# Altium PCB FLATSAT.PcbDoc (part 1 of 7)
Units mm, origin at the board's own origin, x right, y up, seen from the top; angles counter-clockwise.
Board outline 430 x 350 mm, 5 copper layers (Top Layer, Internal Plane 1, Internal Plane 2, DELETEME, Bottom Layer); 808 components, 852 nets, 6407 pads, 939 vias.
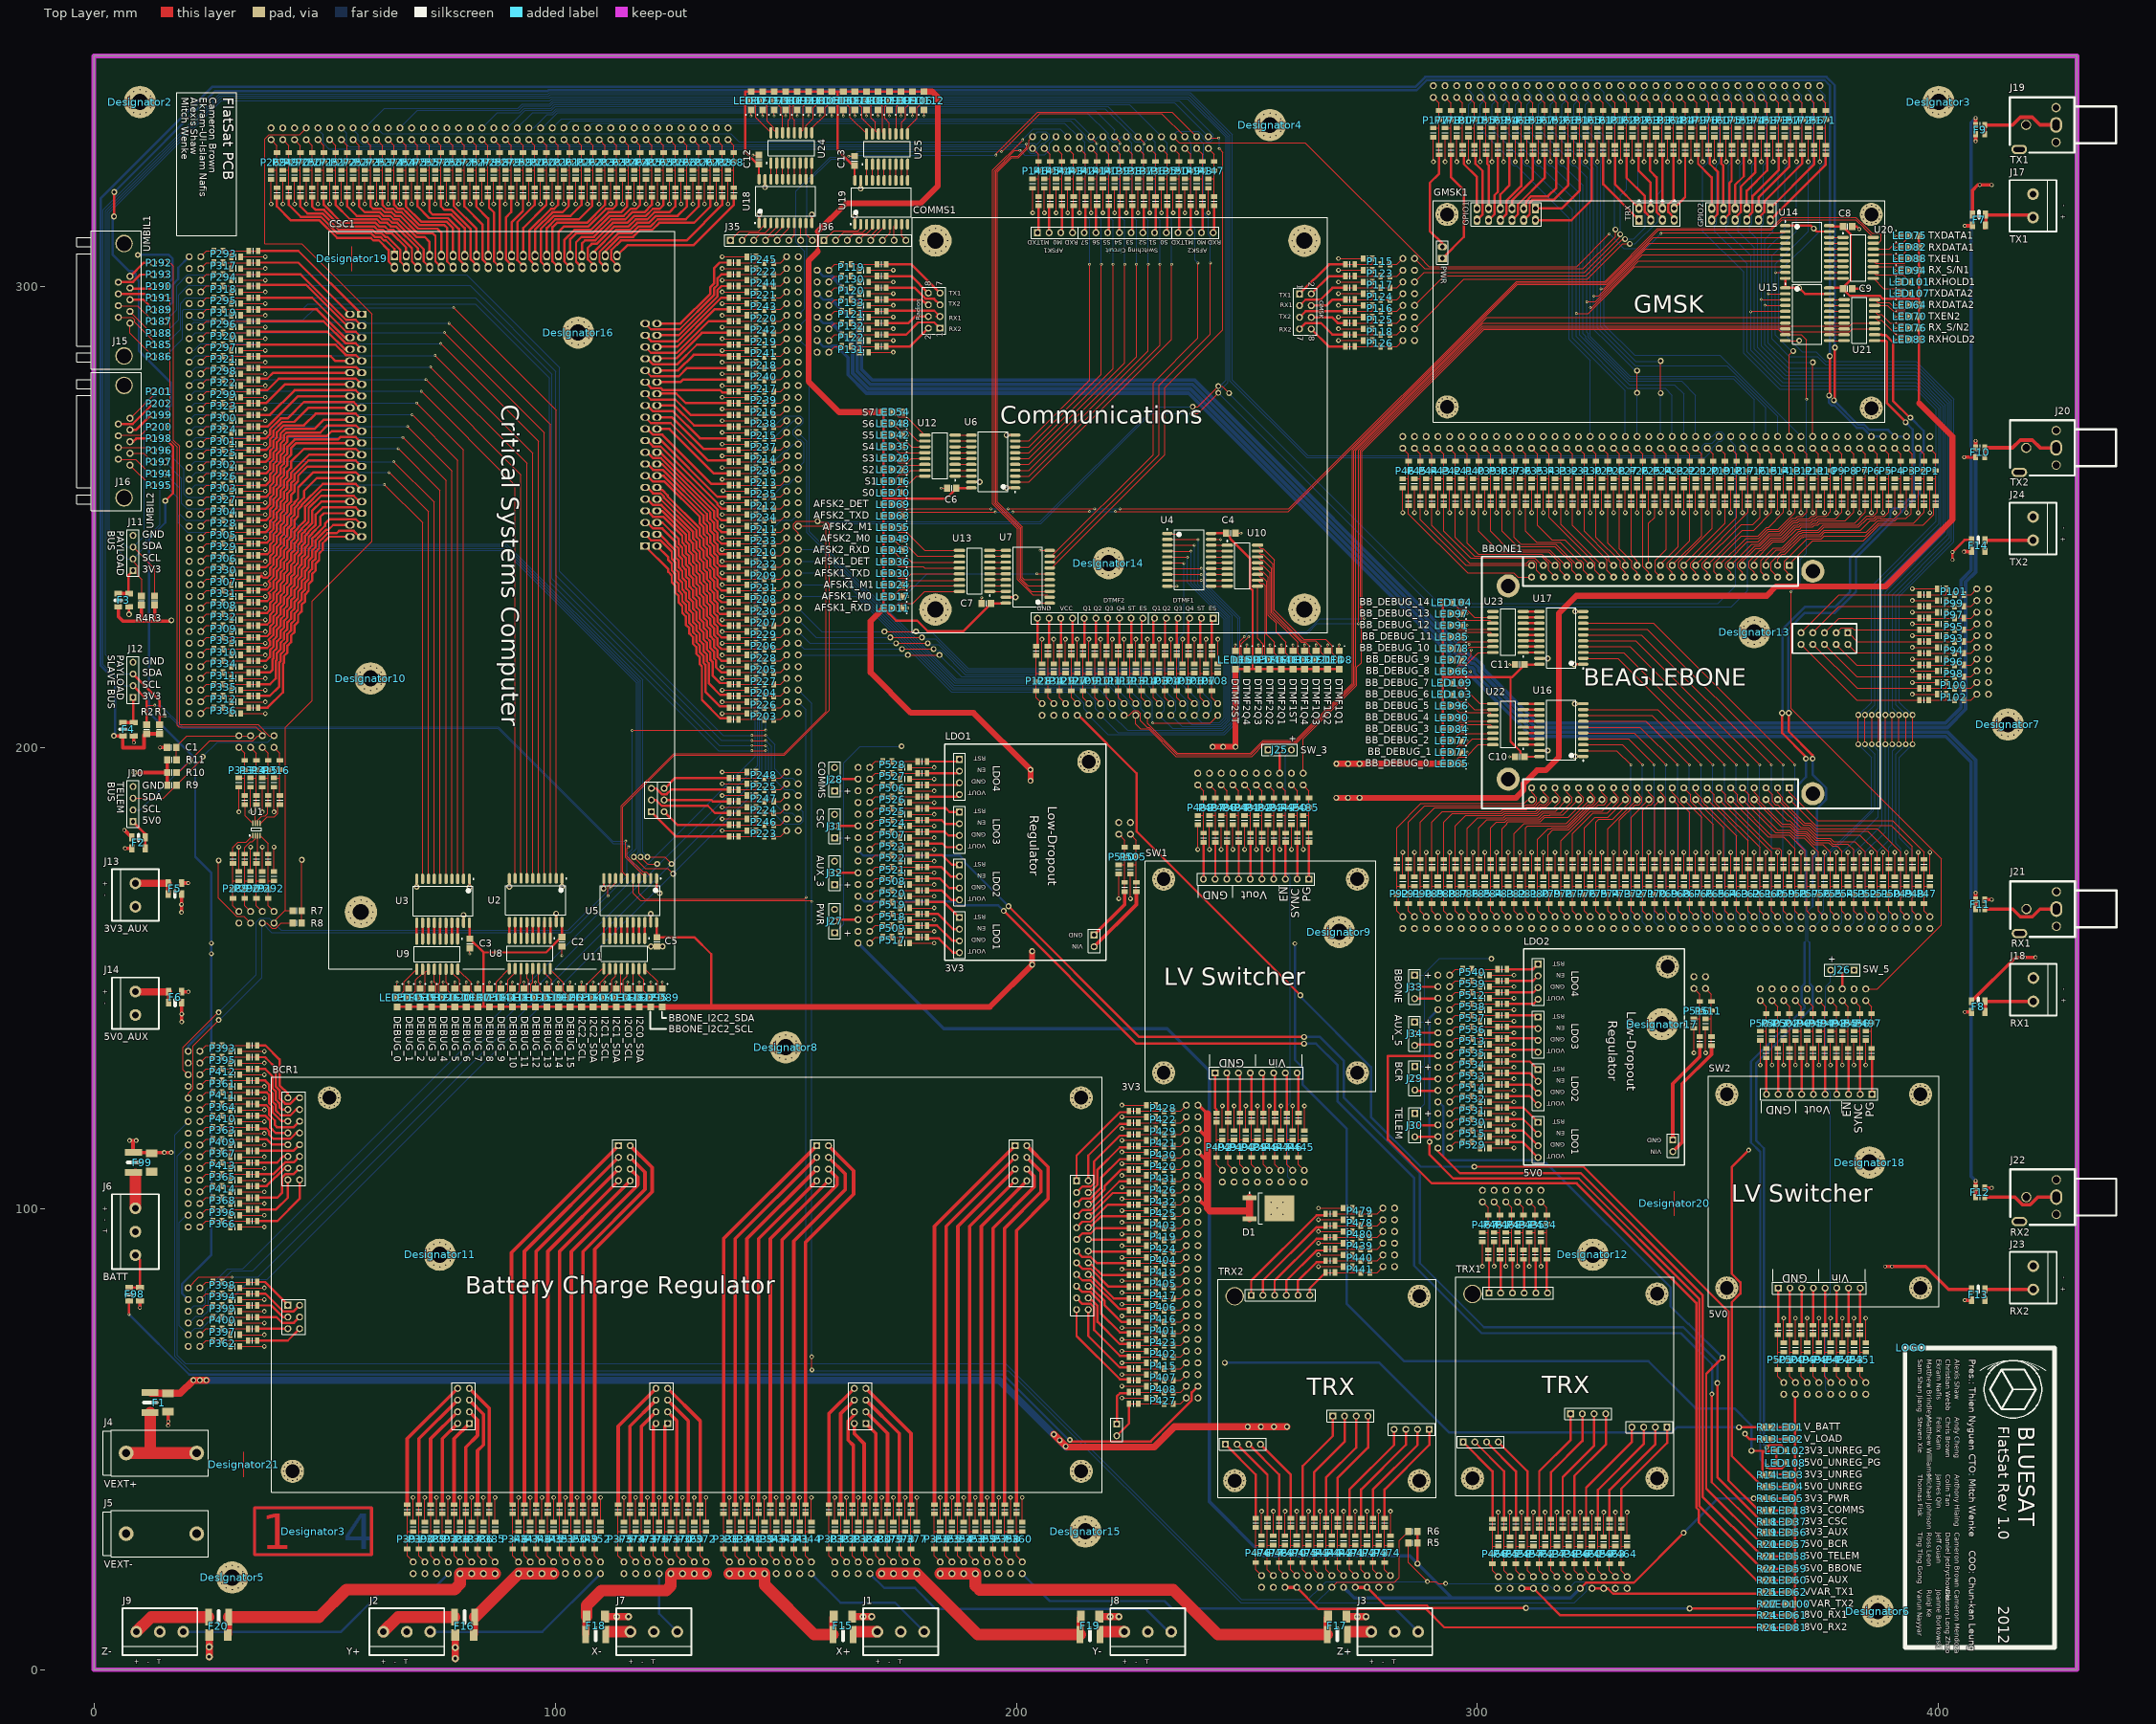
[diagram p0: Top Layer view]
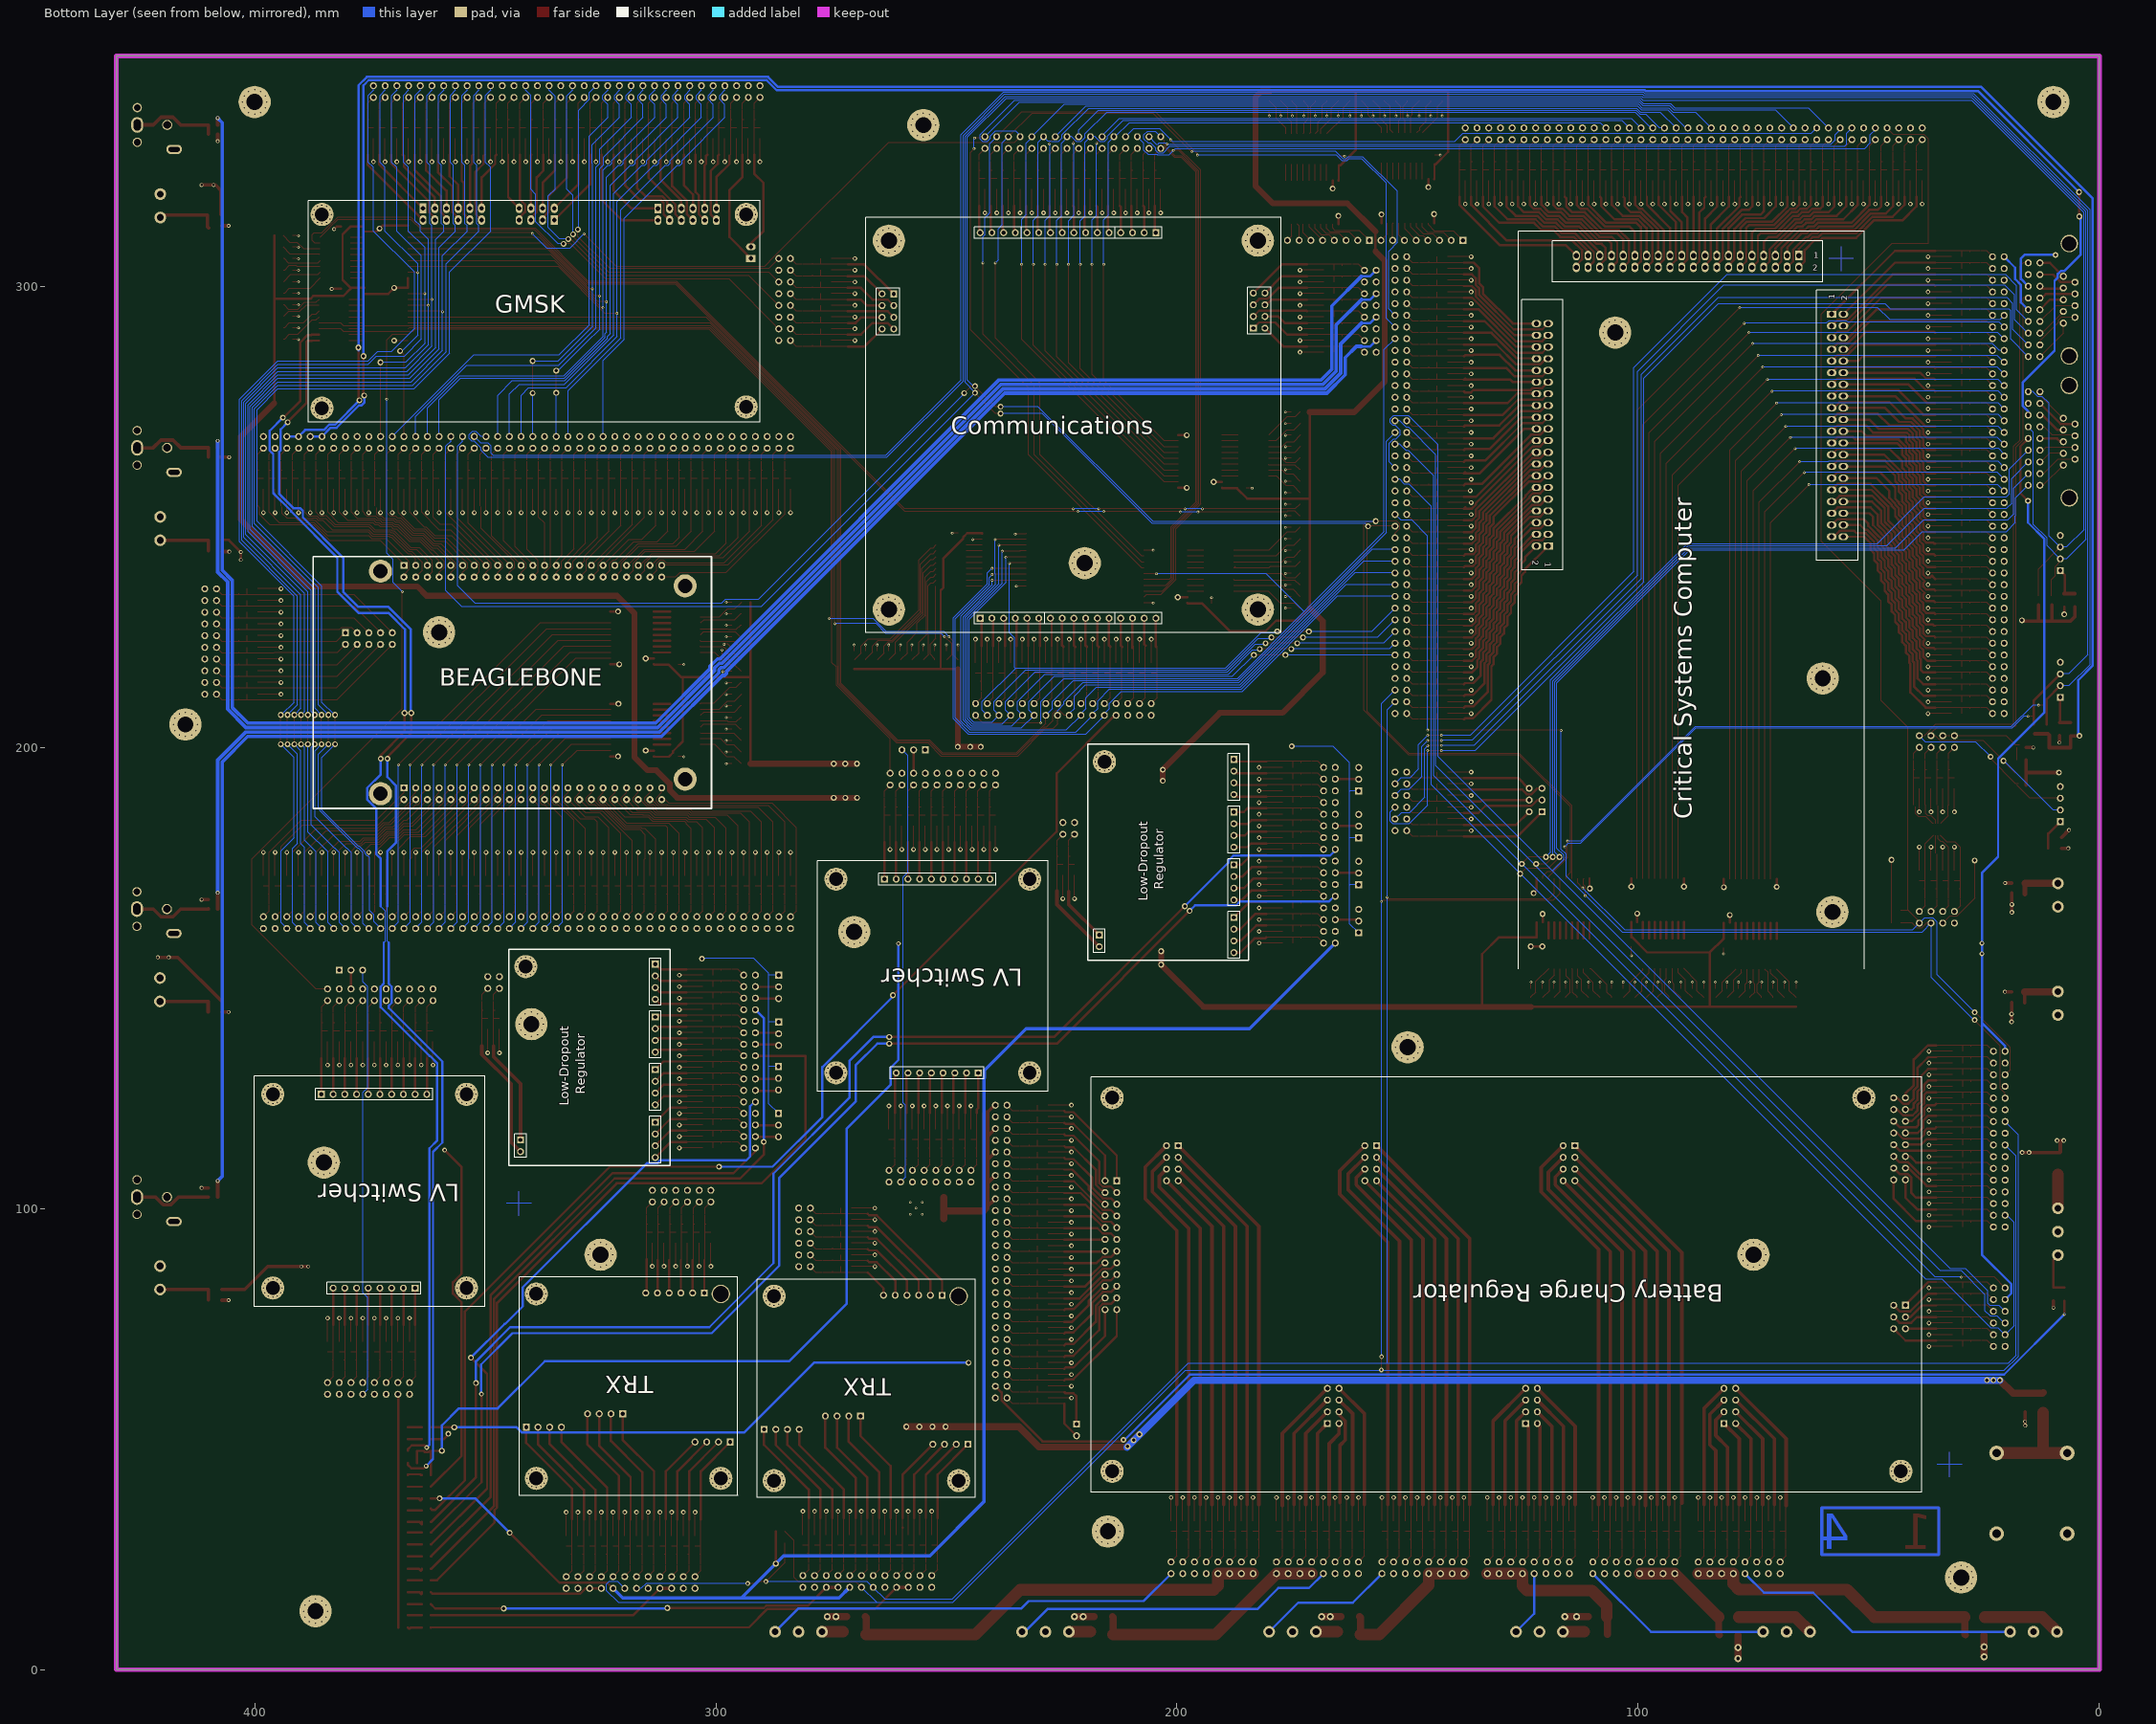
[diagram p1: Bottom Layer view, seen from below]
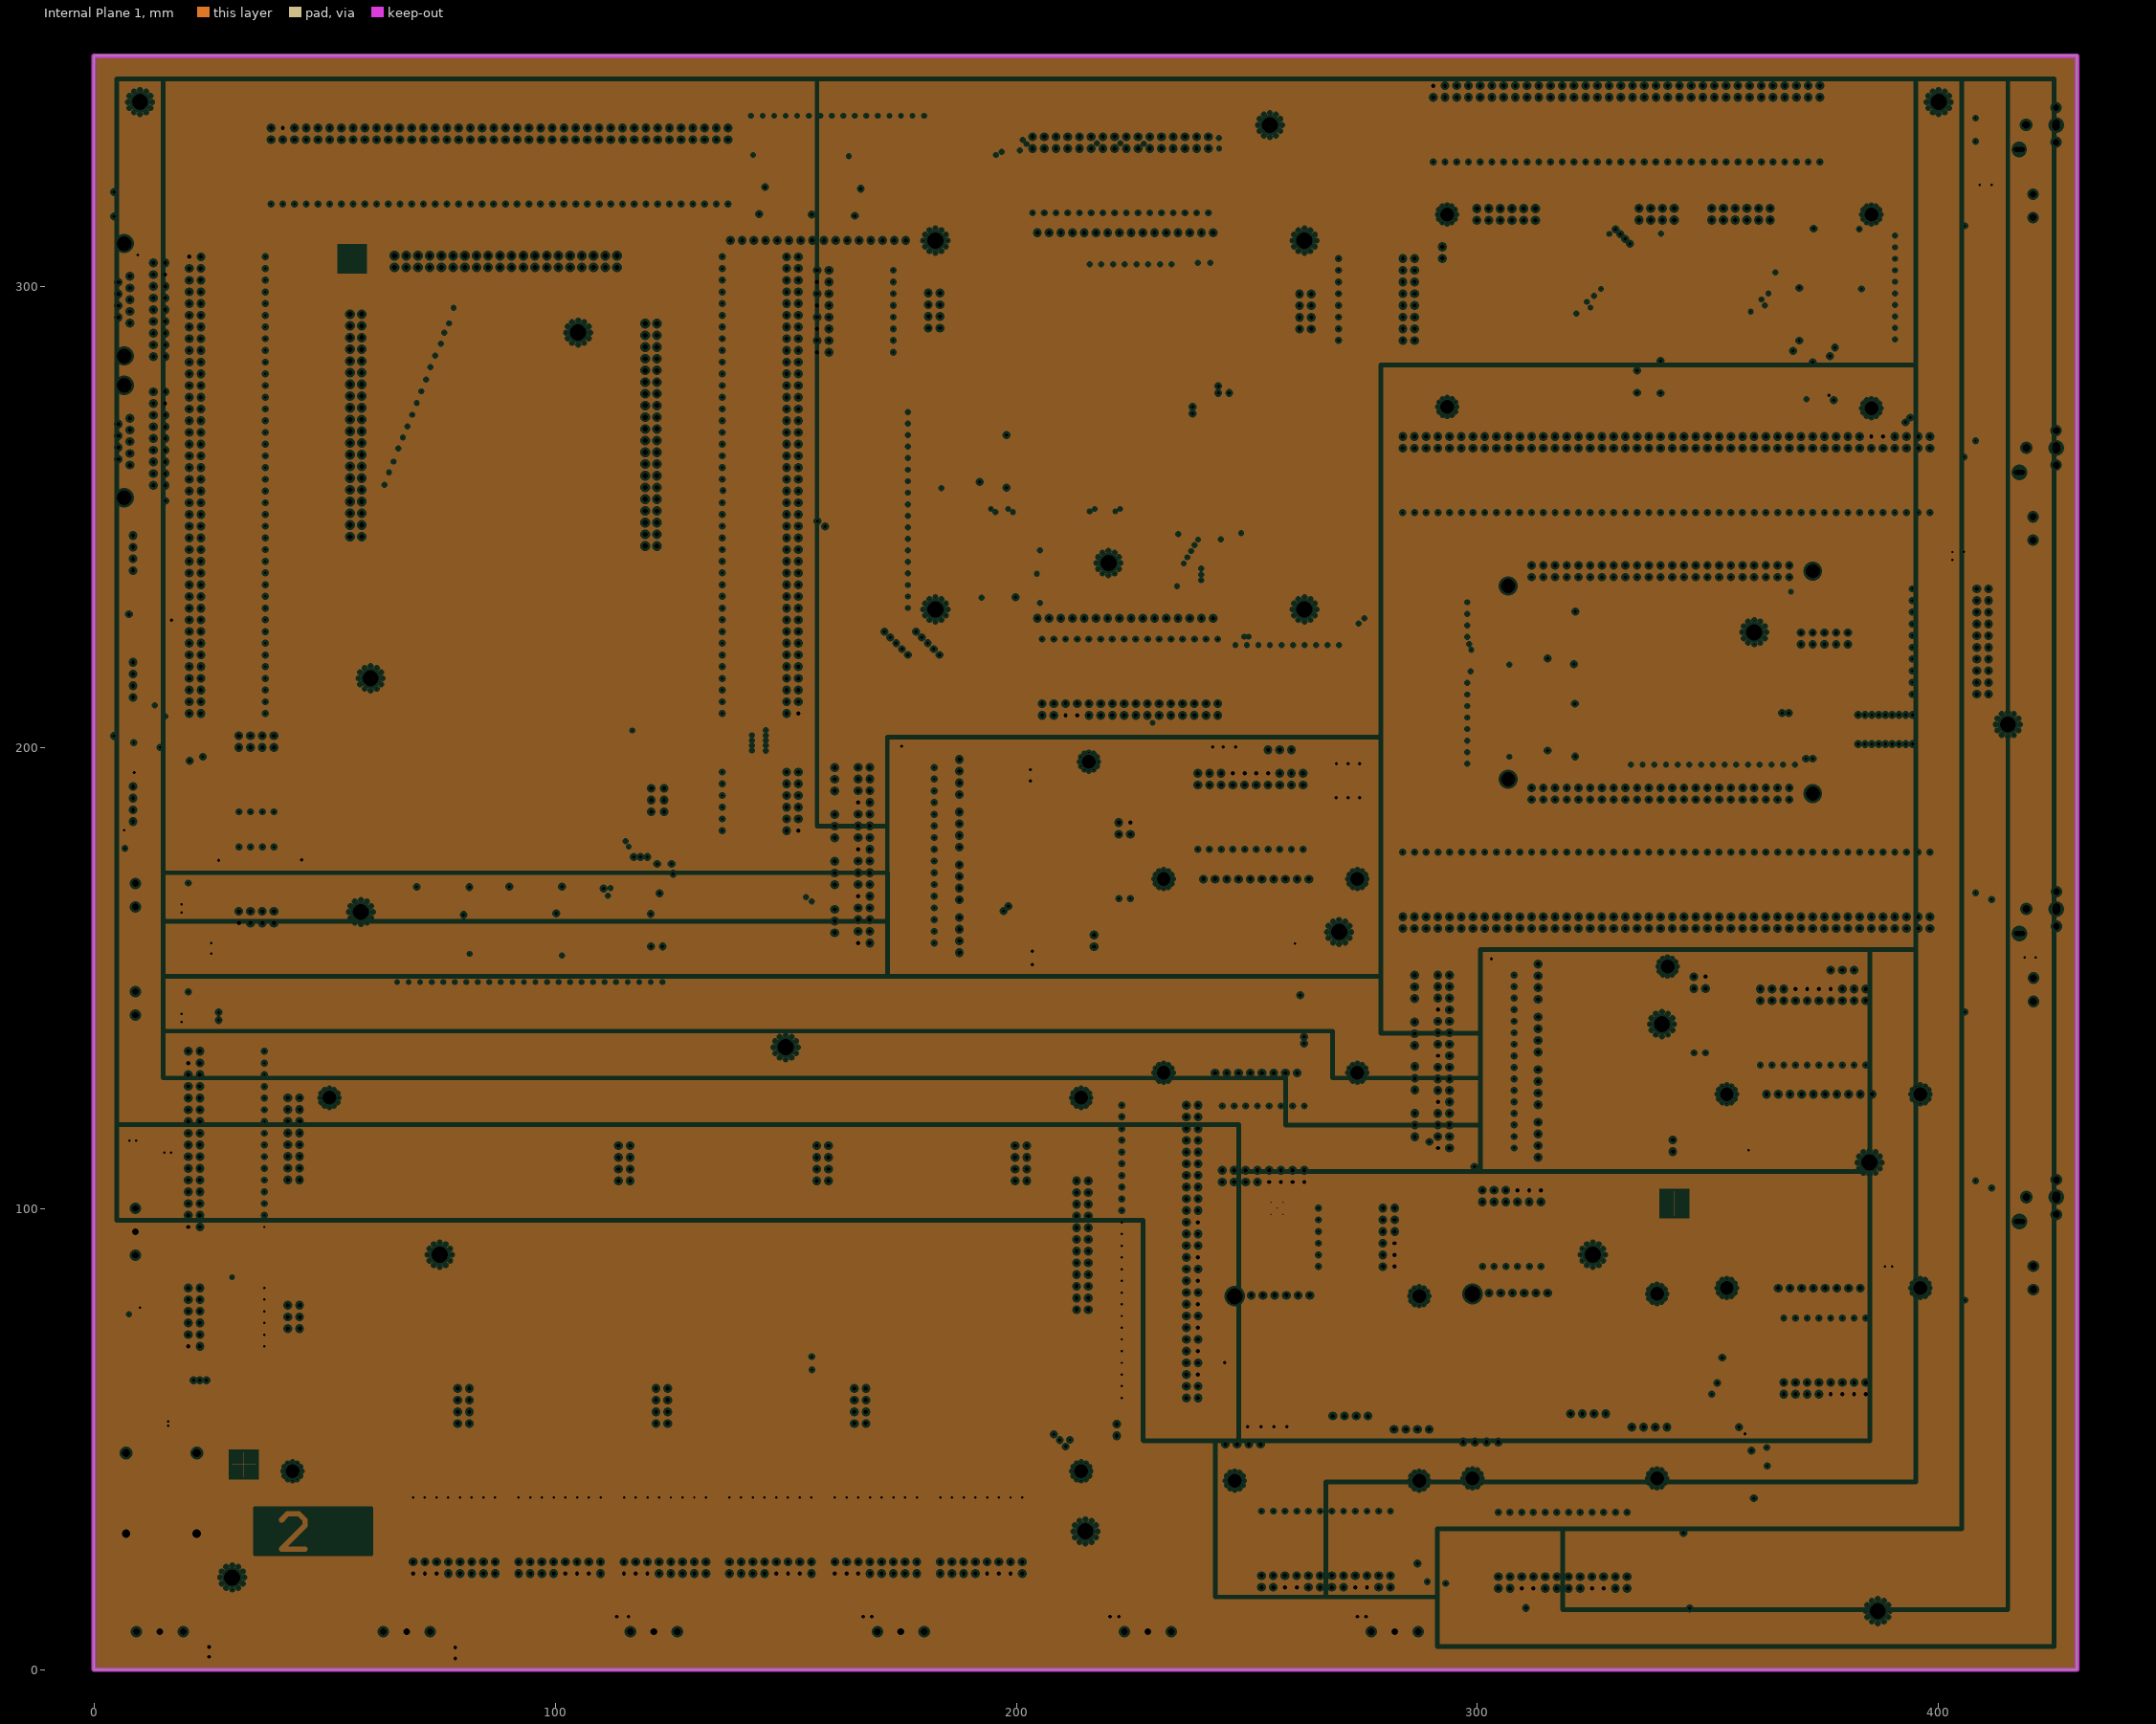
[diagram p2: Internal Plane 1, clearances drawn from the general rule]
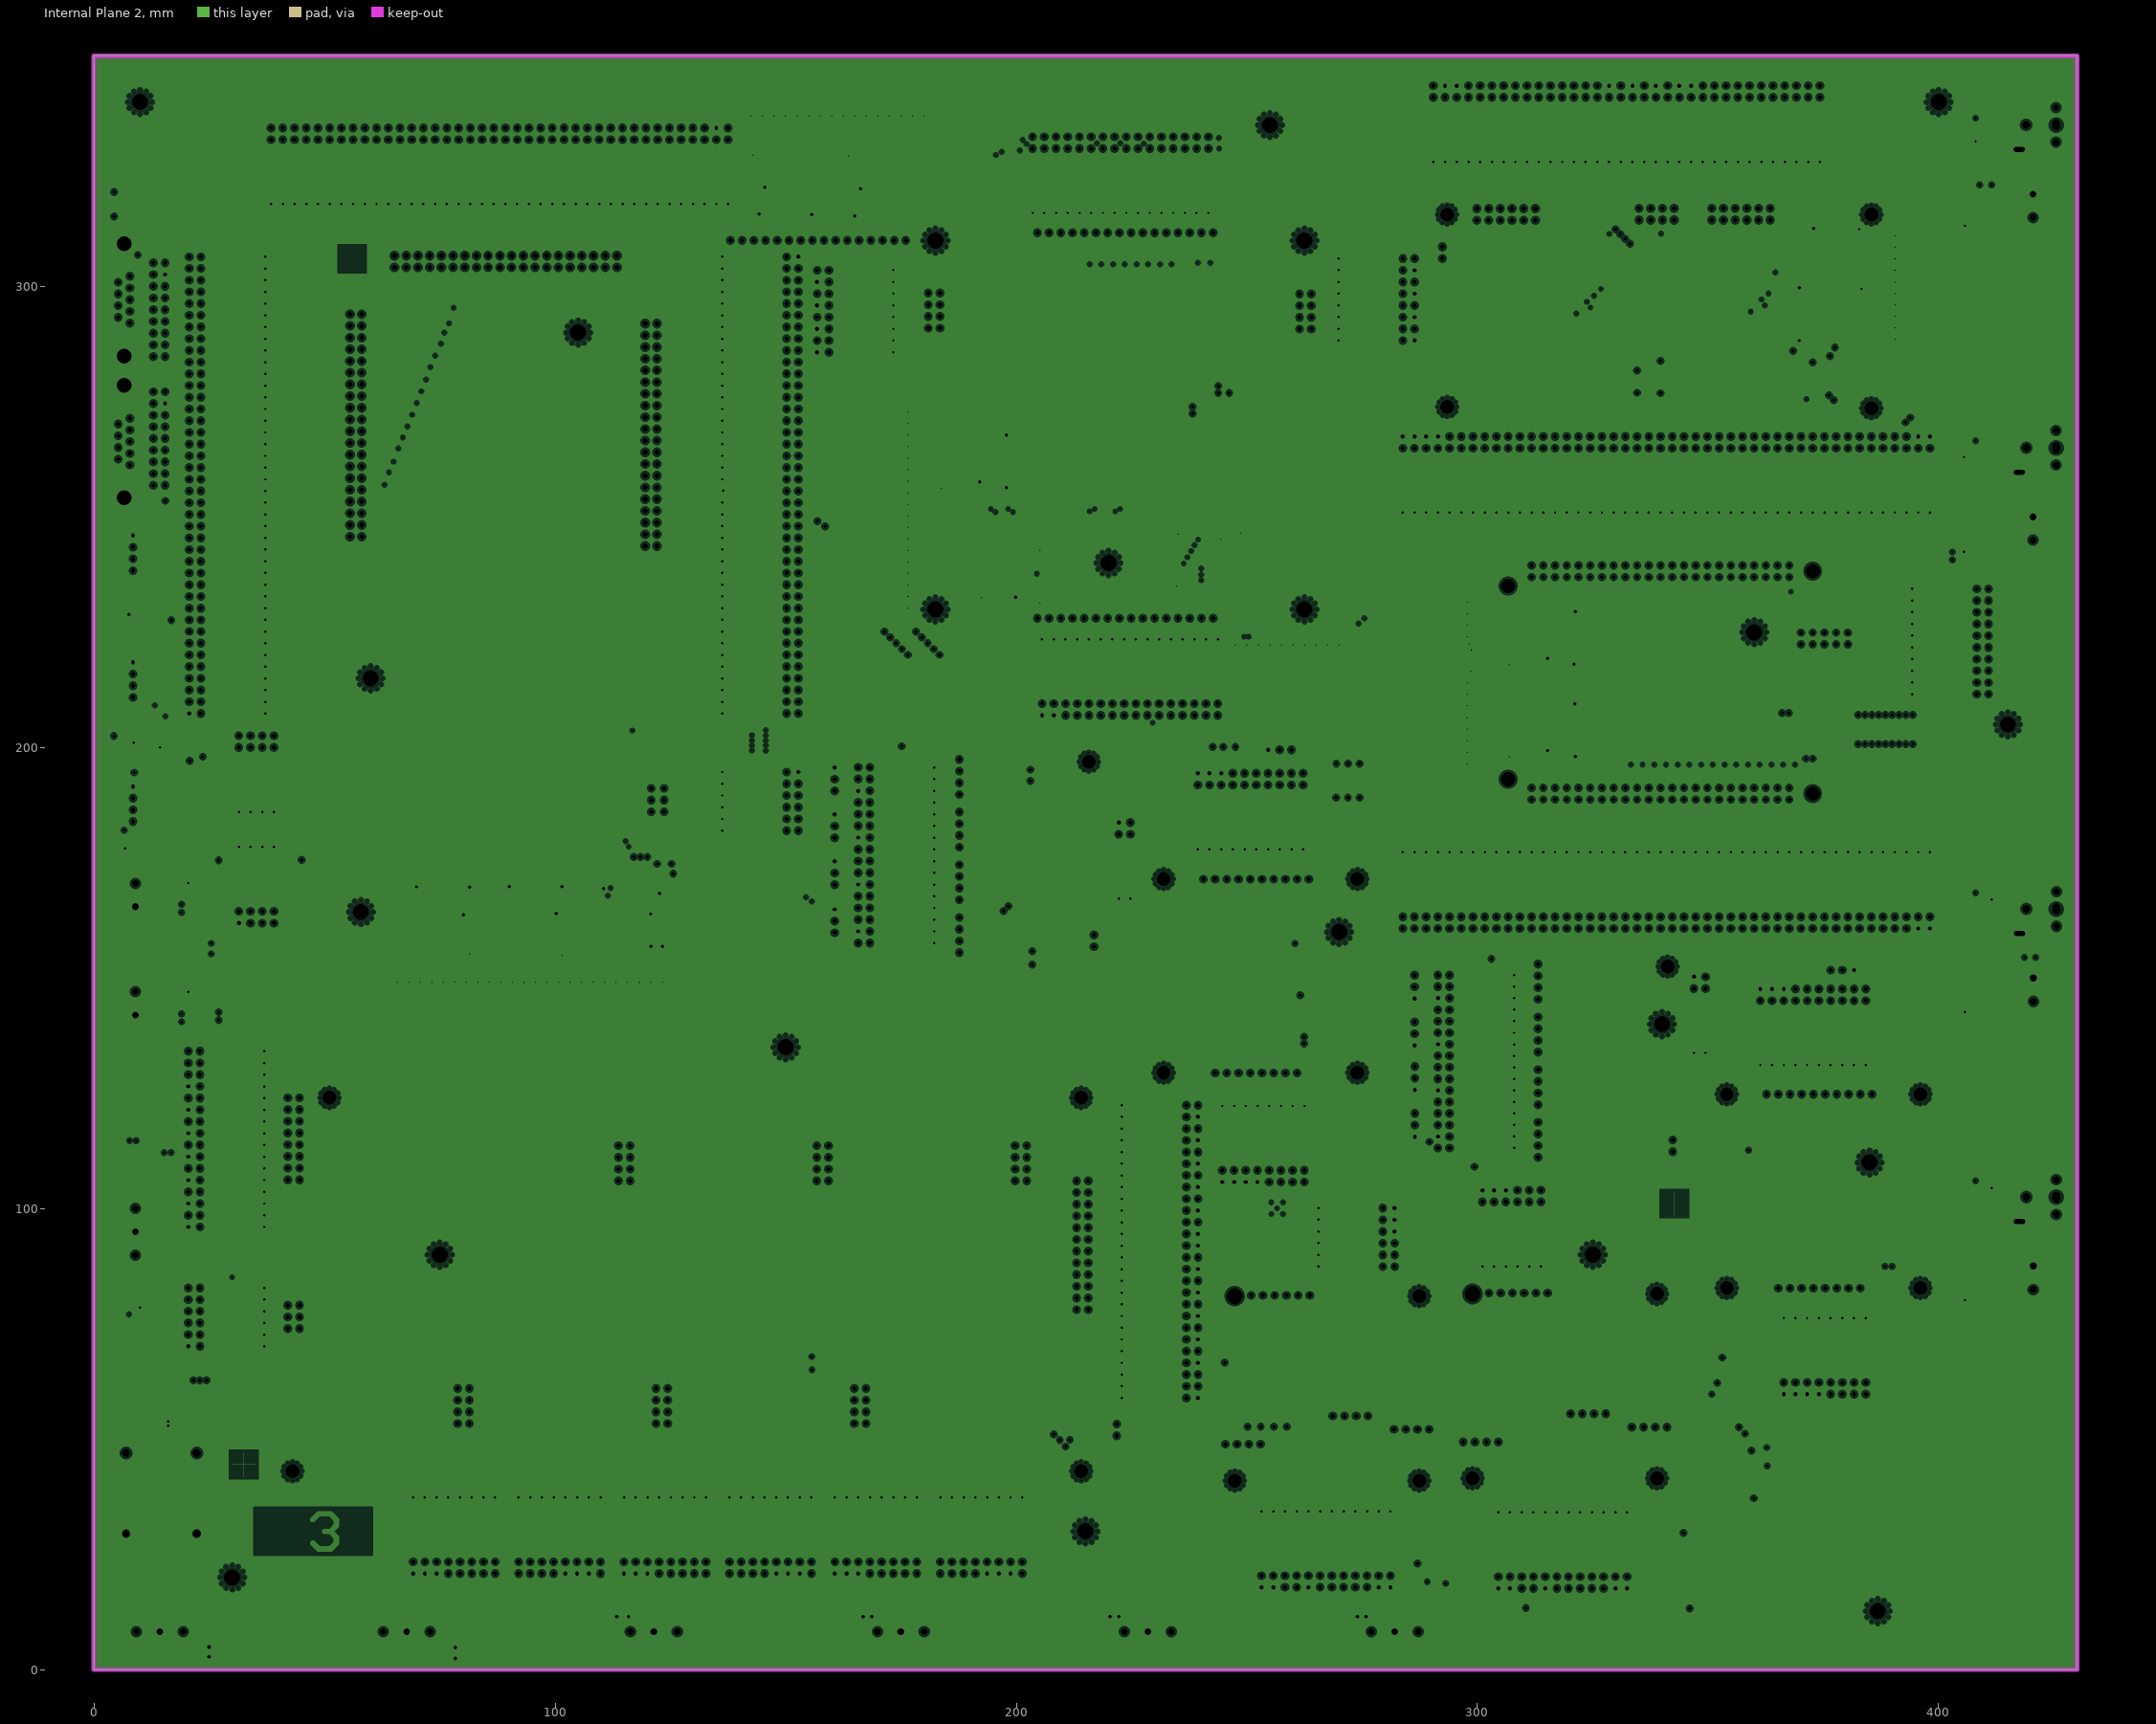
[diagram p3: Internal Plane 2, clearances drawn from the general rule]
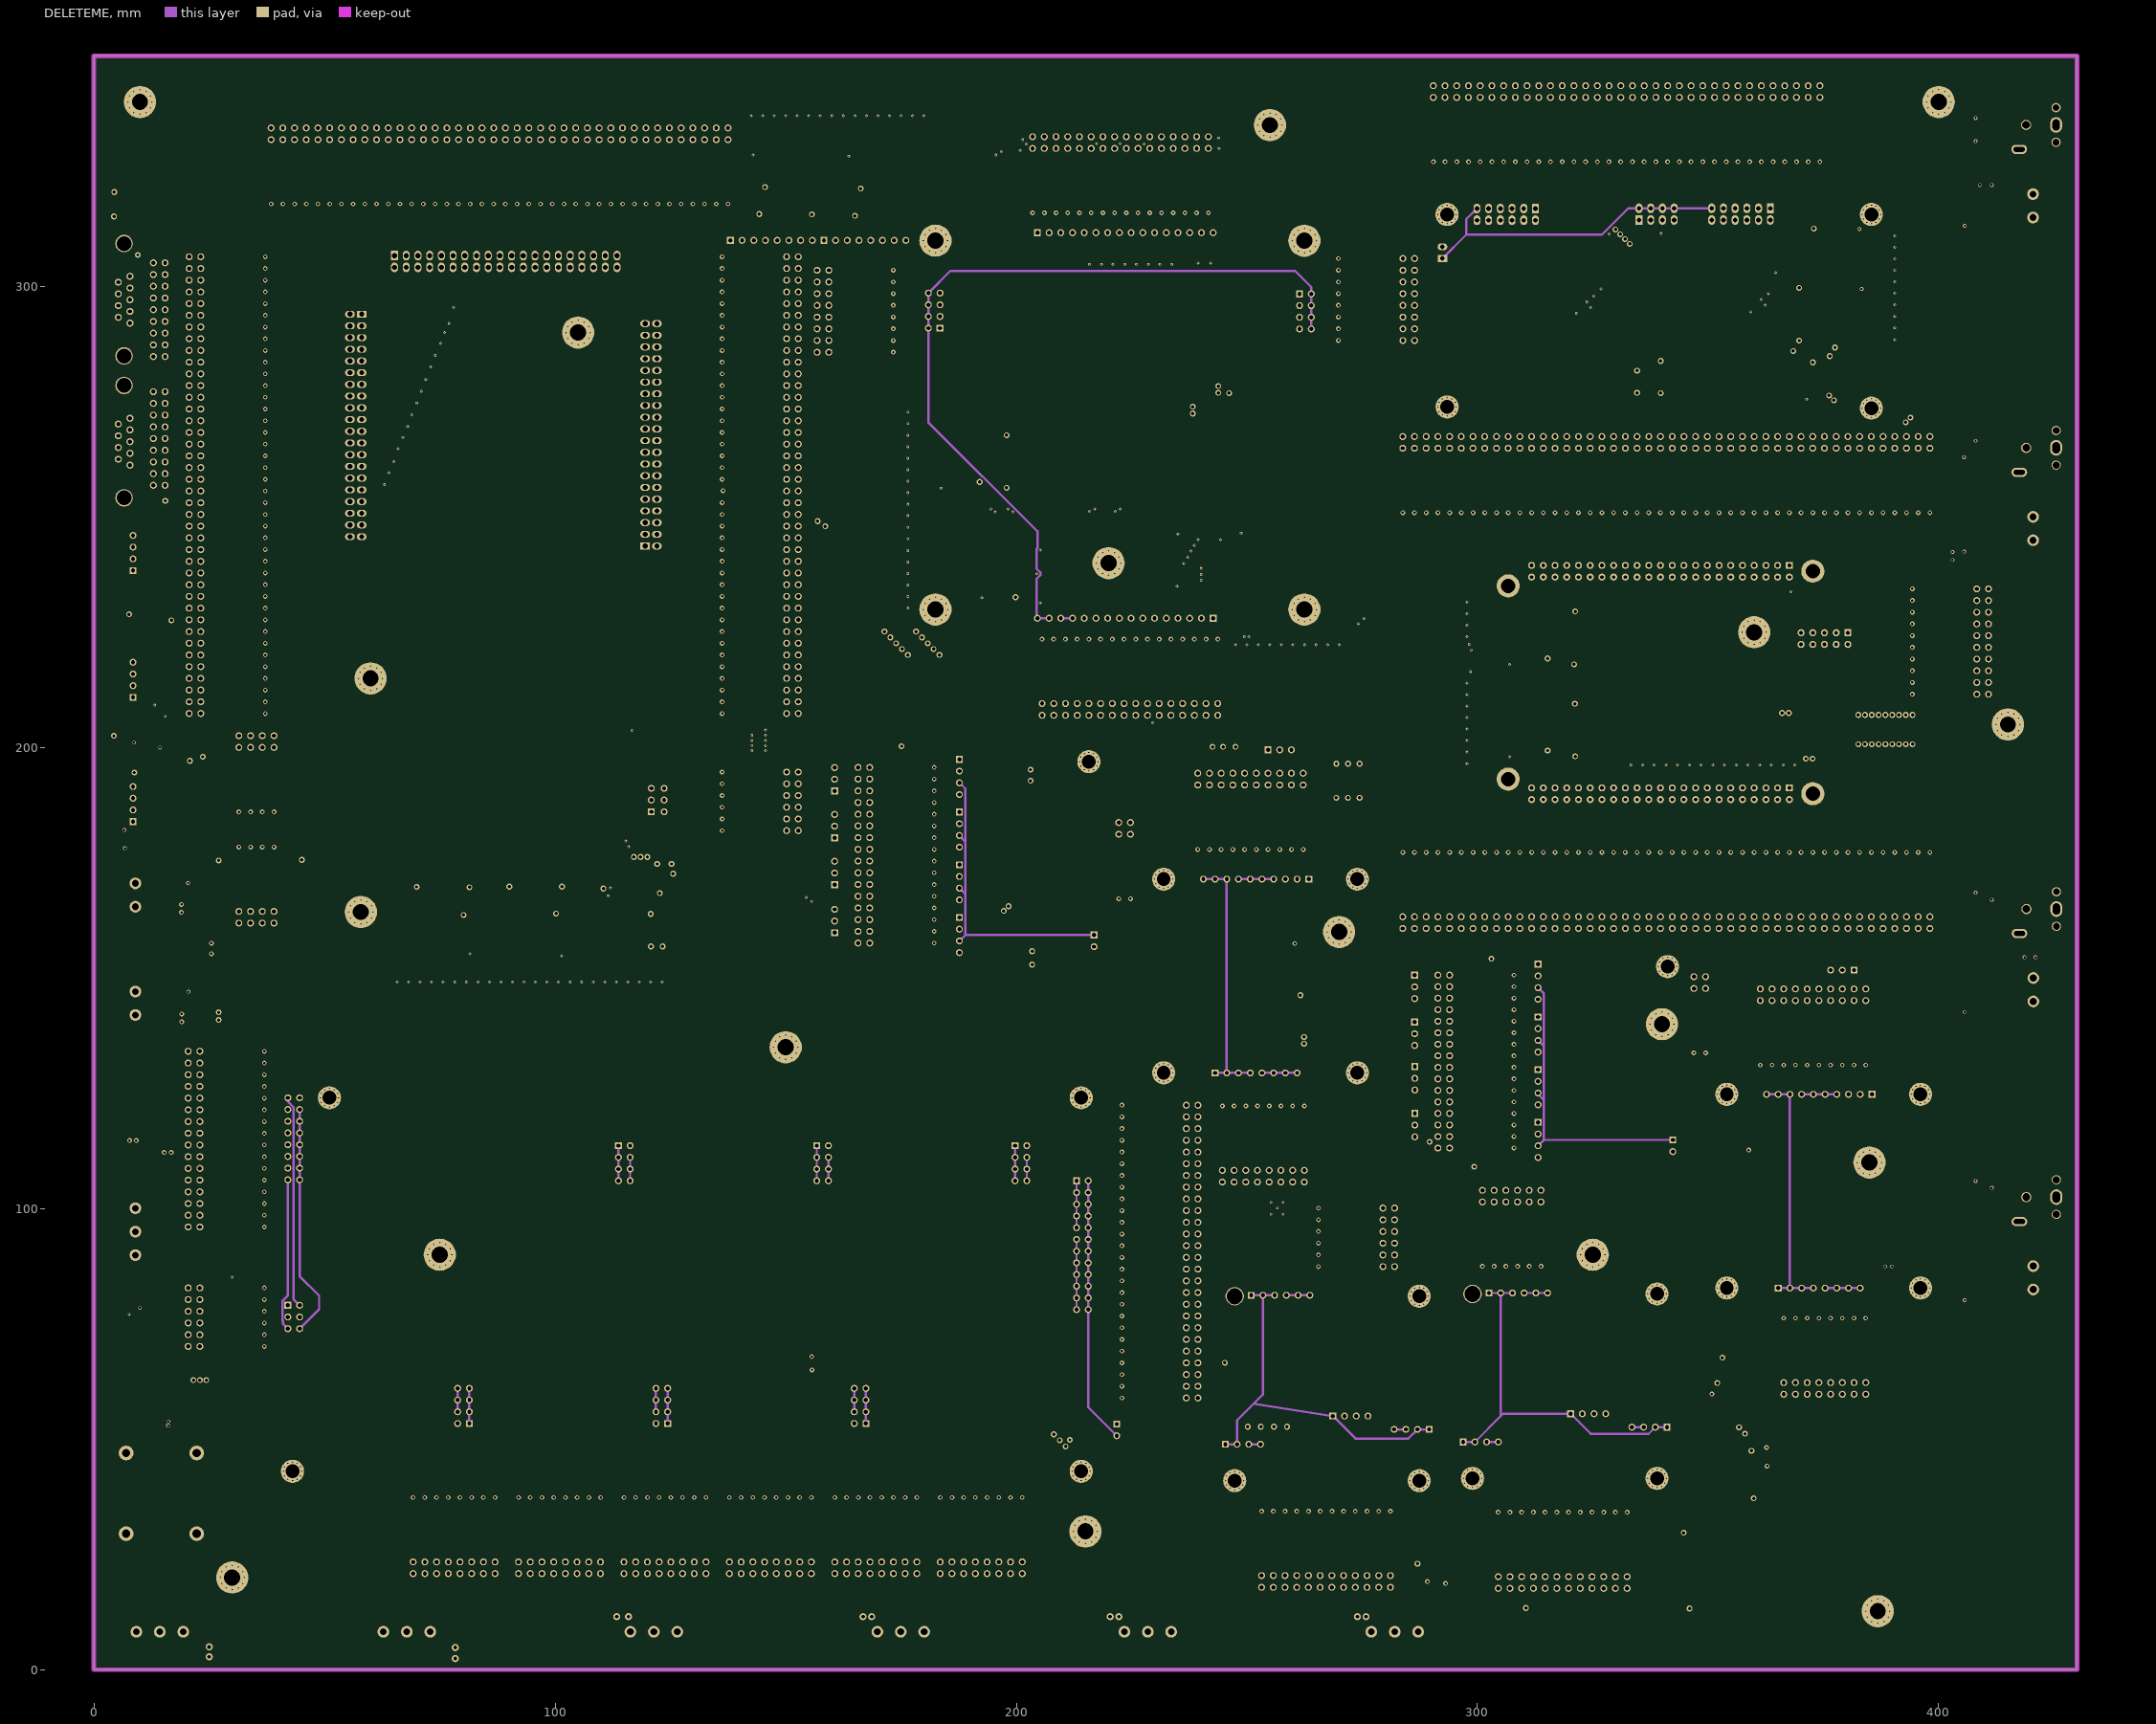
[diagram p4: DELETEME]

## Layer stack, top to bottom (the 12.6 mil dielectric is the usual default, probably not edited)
Top Layer: signal copper 0.0356
Dielectric: core 0.32, FR-4, Dk 4.8
Internal Plane 1: plane copper 0.0356, net (Multiple Nets)
Dielectric: prepreg 0.32, FR-4, Dk 4.8
Internal Plane 2: plane copper 0.0356, net GND
Dielectric: core 0.32, FR-4, Dk 4.8
DELETEME: signal copper 0.0356
Dielectric: prepreg 0.32, FR-4, Dk 4.8
Bottom Layer: signal copper 0.0356

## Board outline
0,0 0,350 430,350 430,0

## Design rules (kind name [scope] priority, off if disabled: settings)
Clearance [All] p1: gap=0.178
HoleSize [All] p1: absolutevalues=TRUE maxlimit=25.4 minlimit=0.025 maxpercent=80.000 minpercent=20.000
MinimumSolderMaskSliver [NOT InNet('GND') vs NOT InNet('GND')] p1: minsoldermaskwidth=0.152
PlaneClearance [All] p1: clearance=0.508
PlaneConnect [All] p1: planeconnectstyle=Relief reliefexpansion=0.508 reliefentries=4 reliefconductorwidth=0.254 reliefairgap=0.254
PolygonConnect [All] p1: connectstyle=Relief reliefconductorwidth=0.254 reliefentries=4 polygonreliefangle="90 Angle"
RoutingVias [All] p1: holewidth=0.711 width=1.27 viastyle="Through Hole" minholewidth=0.508 minwidth=1.016 maxholewidth=0.711 maxwidth=1.27
ShortCircuit ShortCircuit_1 [All] p1: allowed=FALSE
ShortCircuit [All] p2: allowed=FALSE
SilkToSilkClearance [All] p1 off: silktosilkclearance=0.003
SilkscreenOverComponentPads [All] p1: minsilkscreentomaskgap=0.003
SolderMaskExpansion [All] p1: expansion=0.102
Width [All] p1: maxlimit=2.54 minlimit=0.152 preferedwidth=0.508
21 further rules are at their usual default settings.

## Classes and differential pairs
component class LED_BANK_PWR: LED1 LED2 LED3 LED4 LED5 LED18 LED37 LED56 LED57 LED58 LED59 LED60 LED61 LED62 LED81 LED100 R12 R13 R14 R15 R16 R17 R18 R19 R20 R21 R22 R23 R24 R25 R26 R27
component class LED_BANK_12: C13 J36 LED68 LED74 LED80 LED87 LED93 LED99 LED106 LED112 U19 U25
component class LED_BANK_11: C12 J35 LED67 LED73 LED79 LED86 LED92 LED98 LED105 LED111 U18 U24
component class LED_BANK_10: C11 LED66 LED72 LED78 LED85 LED91 LED97 LED104 U17 U23
component class LED_BANK_9: C10 LED65 LED71 LED77 LED84 LED90 LED96 LED103 LED109 U16 U22
component class LED_BANK_8: C9 LED64 LED70 LED76 LED83 LED89 LED95 LED102 LED108 U15 U21
component class LED_BANK_7: C8 LED63 LED69 LED75 LED82 LED88 LED94 LED101 LED107 U14 U20
component class LED_BANK_6: C7 LED11 LED17 LED24 LED30 LED36 LED43 LED49 LED55 U7 U13
component class LED_BANK_5: C6 LED10 LED16 LED23 LED29 LED35 LED42 LED48 LED54 U6 U12
component class LED_BANK_4: C5 LED9 LED15 LED22 LED28 LED34 LED41 LED47 LED53 U5 U11
component class LED_BANK_3: C4 LED8 LED14 LED21 LED27 LED33 LED40 LED46 LED52 U4 U10
component class LED_BANK_2: C3 LED7 LED13 LED20 LED26 LED32 LED39 LED45 LED51 U3 U9
component class LED_BANK_1: C2 LED6 LED12 LED19 LED25 LED31 LED38 LED44 LED50 U2 U8
component class BBONE: BBONE1 P1 P2 P3 P4 P5 P6 P7 P8 P9 P10 P11 P12 P13 P14 P15 P16 P17 P18 P19 P20 P21 P22 P23 P24 P25 P26 P27 P28 P29 P30 P31 P32 P33 P34 P35 P36 P37 P38 P39 P40 P41 P42 P43 P44 P45 P46 P47 P48 P49 P50 P51 P52 P53 P54 P55 P56 P57 P58 P59 P60 P61 P62 P63 P64 P65 P66 P67 P68 P69 P70 P71 P72 P73 P74 P75 P76 P77 P78 P79 P80 P81 P82 P83 P84 P85 P86 P87 P88 P89 P90 P91 P92 P93 P94 P95 P96 P97 P98 P99 P100 P101 P102
component class CONNECTORS: F1 F2 F3 F4 F5 F6 F7 F8 F9 F10 F11 F12 F13 F14 F98 F99 J1 J2 J3 J4 J5 J6 J7 J8 J9 J10 J11 J12 J13 J14 J15 J17 J18 J19 J20 J21 J22 J23 J24 P185 P186 P187 P188 P189 P190 P191 P192 P193 P194 P195 P196 P197 P198 P199 P200 P201 P202
component class CSC: CSC1 P203 P204 P205 P206 P207 P208 P209 P210 P211 P212 P213 P214 P215 P216 P217 P218 P219 P220 P221 P222 P223 P224 P225 P226 P227 P228 P229 P230 P231 P232 P233 P234 P235 P236 P237 P238 P239 P240 P241 P242 P243 P244 P245 P246 P247 P248 P249 P250 P251 P252 P253 P254 P255 P256 P257 P258 P259 P260 P261 P262 P263 P264 P265 P266 P267 P268 P269 P270 P271 P272 P273 P274 P275 P276 P277 P278 P279 P280 P281 P282 P283 P284 P285 P286 P287 P288 P289 P290 P291 P292 P293 P294 P295 P296 P297 P298 P299 P300 P301 P302 P303 P304 P305 P306 P307 P308 P309 P310 P311 P312 P313 P314 P315 P316 P317 P318 P319 P320 P321 P322 P323 P324 P325 P326 P327 P328 P329 P330 P331 P332 P333 P334 P335 P336 R5 R6 R7 R8 U1
component class PWR_GEN: BCR1 D1 F15 F16 F17 F18 F19 F20 P321_1 P337 P338 P339 P340 P341 P342 P343 P344 P345 P346 P347 P348 P349 P350 P351 P352 P353 P354 P355 P356 P357 P358 P359 P360 P361 P362 P363 P364 P365 P366 P367 P368 P369 P370 P371 P372 P373 P374 P375 P376 P377 P378 P379 P380 P381 P382 P383 P384 P385 P386 P387 P388 P389 P390 P391 P392 P393 P394 P395 P396 P397 P398 P399 P400 P401 P402 P403 P404 P405 P406 P407 P408 P409 P410 P411 P412 P413 P414 P415 P416 P417 P418 P419 P420 P421 P422 P423 P424 P425 P426 P427 P428 P429 P430 P431 P432
component class GMSK: GMSK1 P151 P152 P153 P154 P155 P156 P157 P158 P159 P160 P161 P162 P163 P164 P165 P166 P167 P168 P169 P170 P171 P172 P173 P174 P175 P176 P177 P178 P179 P180 P181 P182 P183 P184
component class COMMSB: COMMS1 P103 P104 P105 P106 P107 P108 P109 P110 P111 P112 P113 P114 P115 P116 P117 P118 P119 P120 P121 P122 P123 P124 P125 P126 P127 P128 P129 P130 P131 P132 P133 P134 P135 P136 P137 P138 P139 P140 P141 P142 P143 P144 P145 P146 P147 P148 P149 P150
component class LDO1: J27 J28 J31 J32 LDO1 P505 P506 P507 P508 P509 P510 P517 P518 P519 P520 P521 P522 P523 P524 P525 P526 P527 P528
component class LDO2: J29 J30 J33 J34 LDO2 P511 P512 P513 P514 P515 P516 P529 P530 P531 P532 P533 P534 P535 P536 P537 P538 P539 P540
component class SW1: J25 P445 P446 P447 P448 P449 P450 P481 P482 P483 P484 P485 P486 P487 P488 P489 P490 P491 P492 SW1
component class SW2: J26 P451 P452 P453 P454 P455 P456 P493 P494 P495 P496 P497 P498 P499 P500 P501 P502 P503 P504 SW2
component class TRX1: P433 P434 P435 P436 P437 P438 P457 P458 P459 P460 P461 P462 P463 P464 P465 P466 P467 P468 TRX1
component class TRX2: P439 P440 P441 P442 P443 P444 P469 P470 P471 P472 P473 P474 P475 P476 P477 P478 P479 P480 TRX2

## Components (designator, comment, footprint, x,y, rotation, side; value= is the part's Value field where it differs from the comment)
BBONE1 "Beagle_Bone" Beaglebone 300.943,241.41 r0 top locked
BCR1 "BCR" BCR 218.571,128.532 r180 top locked
C1 "0805 Cap" 6-0805_M 16.875,200.025 r0 top
C2 "" 6-0805_M 101.505,157.875 r90 top
C3 "" 6-0805_M 81.5,157.5 r90 top
C4 "" 6-0805_M 246.5,246.5 r180 top
C5 "" 6-0805_M 122.073,157.85 r90 top
C6 "" 6-0805_M 186,256.25 r0 top
C7 "" 6-0805_M 193.5,231.25 r0 top
C8 "" 6-0805_M 380.25,313 r180 top
C9 "" 6-0805_M 380.25,299.5 r180 top
C10 "" 6-0805_M 309.171,198 r0 top
C11 "" 6-0805_M 309.171,218 r0 top
C12 "" 6-0805_M 144.18,327.5 r270 top
C13 "" 6-0805_M 164.93,327.25 r270 top
COMMS1 "COMMS" Communications 177.473,224.924 r0 top locked
CSC1 "Critical Systems Computer" CSC 50.944,311.951 r270 top locked
D1 "50WQ03FN" TO229P990X238-3N 254.648,100.076 r0 top
Designator2 "Comment" HOLE3.5 10,340 r0 top
Designator3 "Comment" "Layer Plot" 47.5,30 r0 top
Designator3 "Comment" HOLE3.5 400,340 r0 top
Designator4 "Comment" HOLE3.5 255,335 r0 top
Designator5 "Comment" HOLE3.5 30,20 r0 top
Designator6 "Comment" HOLE3.5 386.8,12.7 r0 top
Designator7 "Comment" HOLE3.5 415,205 r0 top
Designator8 "Comment" HOLE3.5 150,135 r0 top
Designator9 "Comment" HOLE3.5 270,160 r0 top
Designator10 "Comment" HOLE3.5 60,215 r0 top
Designator11 "Comment" HOLE3.5 75,90 r0 top
Designator12 "Comment" HOLE3.5 325,90 r0 top
Designator13 "Comment" HOLE3.5 360,225 r0 top
Designator14 "Comment" HOLE3.5 220,240 r0 top
Designator15 "Comment" HOLE3.5 215,30 r0 top
Designator16 "Comment" HOLE3.5 105,290 r0 top
Designator17 "Comment" HOLE3.5 340,140 r0 top
Designator18 "Comment" HOLE3.5 385,110 r0 top
Designator19 "Comment" "Registration Check" 56,306 r0 top
Designator20 "Comment" "Registration Check" 342.7,101.1 r0 top
Designator21 "Comment" "Registration Check" 32.5,44.5 r0 top
F1 "FilterSola" FILTERSOLA 16.097,57.94 r90 top
F2 "FilterPwr" FILTERPWR 9.675,178.15 r0 top
F3 "FilterPwr" FILTERPWR 7.645,231.953 r90 top
F4 "FilterPwr" FILTERPWR 8.636,203.962 r90 top
F5 "FilterPwr" FILTERPWR 17.575,170.6 r180 top
F6 "FilterPwr" FILTERPWR 17.624,147.036 r180 top
F7 "FilterPwr" FILTERPWR 408.75,313.25 r0 top
F8 "FilterPwr" FILTERPWR 408.575,142.65 r0 top
F9 "Filter" Filter 409,333 r0 top
F10 "Filter" Filter 409,263 r0 top
F11 "Filter" Filter 409,167 r180 top
F12 "Filter" Filter 409,104.5 r180 top
F13 "FilterPwr" FILTERPWR 408.575,80.15 r0 top
F14 "FilterPwr" FILTERPWR 408.575,242.65 r0 top
F15 "FilterSola" FILTERSOLA 162.417,11.52 r180 top
F16 "FilterSola" FILTERSOLA 80.375,7.53 r0 top
F17 "FilterSola" FILTERSOLA 269.605,11.52 r180 top
F18 "FilterSola" FILTERSOLA 108.823,11.52 r180 top
F19 "FilterSola" FILTERSOLA 216.011,11.52 r180 top
F20 "FilterSola" FILTERSOLA 27.035,7.53 r0 top
F98 "FilterPwr" FILTERPWR 10,81.425 r90 top
F99 "FilterSola" FILTERSOLA 12.5,110 r90 top
GMSK1 "GMSK" GMSK 290.428,269.87 r0 top locked
J1 "X+" SCREW3 174.96,8.23 r0 top
J2 "Y+" SCREW3 67.854,8.23 r0 top
J3 "Z+" SCREW3 282.067,8.23 r0 top
J4 "VEXT+" 4MM_BANANA 22.3,47 r180 top
J5 "VEXT-" 4MM_BANANA 22.3,29.5 r180 top
J6 "BATT" SCREW3 9,95 r270 top
J7 "X-" SCREW3 121.407,8.23 r0 top
J8 "Y-" SCREW3 228.514,8.23 r0 top
J9 "Z-" SCREW3 14.3,8.23 r0 top
J10 "TELEM_BUS" HDR1X4 8.5,183.92 r90 top
J11 "PAYLOAD_BUS" HDR1X4 8.5,238.38 r90 top
J12 "PAYLOAD_SLAVE_BUS" HDR1X4 8.5,210.88 r90 top
J13 "3V3_AUX" SCREW2 9,168 r270 top
J14 "5V0_AUX" SCREW2 9,144.54 r270 top
J15 "UMBIL1" "D9 - temp" 7.832,297.112 r90 top
J16 "UMBIL2" "D9 - temp" 7.832,266.338 r90 top
J17 "TX1" SCREW2 420.449,317.488 r90 top
J18 "RX1" SCREW2 420.525,147.475 r90 top
J19 "TX1" "R/A RCA" 425.449,335.028 r270 top
J20 "TX2" "R/A RCA" 425.475,264.998 r270 top
J21 "RX1" "R/A RCA" 425.525,164.975 r270 top
J22 "RX2" "R/A RCA" 425.5,102.5 r270 top
J23 "RX2" SCREW2 420.5,85 r90 top
J24 "TX2" SCREW2 420.475,247.498 r90 top
J25 "SW_3" HDR1X3 254.588,199.5 r0 top
J26 "SW_5" HDR1X3 381.644,151.732 r180 top
J27 "PWR" HDR1X3 160.608,159.836 r90 top
J28 "COMMS" HDR1X3 160.608,190.57 r90 top
J29 "BCR" HDR1X3 286.418,130.8 r270 top
J30 "TELEM" HDR1X3 286.418,120.64 r270 top
J31 "CSC" HDR1X3 160.608,180.41 r90 top
J32 "AUX_3" HDR1X3 160.608,170.25 r90 top
J33 "BBONE" HDR1X3 286.389,150.63 r270 top
J34 "AUX_5" HDR1X3 286.389,140.47 r270 top
J35 "LED_AUX_0-7" HDR1X8 138,310 r0 top
J36 "LED_AUX_8-15" HDR1X8 158.28,310 r0 top
LDO1 "3V3" LDO 219.421,200.738 r180 top locked
LDO2 "5V0" LDO 344.894,156.304 r180 top locked
LED1 "V_BATT" 6-0805_M 367.803,52.585 r0 top
LED2 "V_LOAD" 6-0805_M 367.803,49.965 r0 top
LED3 "3V3_UNREG" 6-0805_M 367.803,42.265 r0 top
LED4 "5V0_UNREG" 6-0805_M 367.803,39.685 r0 top
LED5 "3V3_PWR" 6-0805_M 367.803,37.105 r0 top
LED6 "DEBUG_15" "BIDIRECTIONAL LED" 103.25,146.75 r270 top
LED7 "DEBUG_7" "BIDIRECTIONAL LED" 83.25,146.75 r270 top
LED8 "DTMF1Q1" "BIDIRECTIONAL LED" 270,220 r270 top
LED9 "DTMF2Q4" "BIDIRECTIONAL LED" 250,220 r270 top
LED10 "S0" "BIDIRECTIONAL LED" 174.25,255.25 r180 top
LED11 "AFSK1_RXD" "BIDIRECTIONAL LED" 174.25,230.25 r180 top
LED12 "DEBUG_14" "BIDIRECTIONAL LED" 100.75,146.75 r270 top
LED13 "DEBUG_6" "BIDIRECTIONAL LED" 80.75,146.75 r270 top
LED14 "DTMF1Q2" "BIDIRECTIONAL LED" 267.5,220 r270 top
LED15 "DTMF2ST" "BIDIRECTIONAL LED" 247.5,220 r270 top
LED16 "S1" "BIDIRECTIONAL LED" 174.25,257.75 r180 top
LED17 "AFSK1_M0" "BIDIRECTIONAL LED" 174.25,232.75 r180 top
LED18 "3V3_COMMS" 6-0805_M 367.803,34.525 r0 top
LED19 "DEBUG_13" "BIDIRECTIONAL LED" 98.25,146.75 r270 top
LED20 "DEBUG_5" "BIDIRECTIONAL LED" 78.25,146.75 r270 top
LED21 "DTMF1Q3" "BIDIRECTIONAL LED" 265,220 r270 top
LED22 "I2C0_SDA" "BIDIRECTIONAL LED" 118.25,146.75 r270 top
LED23 "S2" "BIDIRECTIONAL LED" 174.25,260.25 r180 top
LED24 "AFSK1_M1" "BIDIRECTIONAL LED" 174.25,235.25 r180 top
LED25 "DEBUG_12" "BIDIRECTIONAL LED" 95.75,146.75 r270 top
LED26 "DEBUG_4" "BIDIRECTIONAL LED" 75.75,146.75 r270 top
LED27 "DTMF1Q4" "BIDIRECTIONAL LED" 262.5,220 r270 top
LED28 "I2C0_SCL" "BIDIRECTIONAL LED" 115.75,146.75 r270 top
LED29 "S3" "BIDIRECTIONAL LED" 174.25,262.75 r180 top
LED30 "AFSK1_TXD" "BIDIRECTIONAL LED" 174.25,237.75 r180 top
LED31 "DEBUG_11" "BIDIRECTIONAL LED" 93.25,146.75 r270 top
LED32 "DEBUG_3" "BIDIRECTIONAL LED" 73.25,146.75 r270 top
LED33 "DTMF1ST" "BIDIRECTIONAL LED" 260,220 r270 top
LED34 "I2C1_SDA" "BIDIRECTIONAL LED" 113.25,146.75 r270 top
LED35 "S4" "BIDIRECTIONAL LED" 174.25,265.25 r180 top
LED36 "AFSK1_DET" "BIDIRECTIONAL LED" 174.25,240.25 r180 top
LED37 "3V3_CSC" 6-0805_M 367.803,32.025 r0 top
LED38 "DEBUG_10" "BIDIRECTIONAL LED" 90.75,146.75 r270 top
LED39 "DEBUG_2" "BIDIRECTIONAL LED" 70.75,146.75 r270 top
LED40 "DTMF2Q1" "BIDIRECTIONAL LED" 257.5,220 r270 top
LED41 "I2C1_SCL" "BIDIRECTIONAL LED" 110.75,146.75 r270 top
LED42 "S5" "BIDIRECTIONAL LED" 174.25,267.75 r180 top
LED43 "AFSK2_RXD" "BIDIRECTIONAL LED" 174.25,242.75 r180 top
LED44 "DEBUG_9" "BIDIRECTIONAL LED" 88.25,146.75 r270 top
LED45 "DEBUG_1" "BIDIRECTIONAL LED" 68.25,146.75 r270 top
LED46 "DTMF2Q2" "BIDIRECTIONAL LED" 255,220 r270 top
LED47 "I2C2_SDA" "BIDIRECTIONAL LED" 108.25,146.75 r270 top
LED48 "S6" "BIDIRECTIONAL LED" 174.25,270.25 r180 top
LED49 "AFSK2_M0" "BIDIRECTIONAL LED" 174.25,245.25 r180 top
LED50 "DEBUG_8" "BIDIRECTIONAL LED" 85.75,146.75 r270 top
LED51 "DEBUG_0" "BIDIRECTIONAL LED" 65.75,146.75 r270 top
LED52 "DTMF2Q3" "BIDIRECTIONAL LED" 252.5,220 r270 top
LED53 "I2C2_SCL" "BIDIRECTIONAL LED" 105.75,146.75 r270 top
LED54 "S7" "BIDIRECTIONAL LED" 174.25,272.75 r180 top
LED55 "AFSK2_M1" "BIDIRECTIONAL LED" 174.25,247.75 r180 top
LED56 "3V3_AUX" 6-0805_M 367.803,29.765 r0 top
LED57 "5V0_BCR" 6-0805_M 367.803,27.185 r0 top
LED58 "5V0_TELEM" 6-0805_M 367.803,24.605 r0 top
LED59 "5V0_BBONE" 6-0805_M 367.803,21.865 r0 top
LED60 "5V0_AUX" 6-0805_M 367.803,19.445 r0 top
LED61 "8V0_RX1" 6-0805_M 367.803,11.785 r0 top
LED62 "VVAR_TX1" 6-0805_M 367.803,16.825 r0 top
LED63 "AFSK2_TXD" "BIDIRECTIONAL LED" 174.25,250.25 r180 top
LED64 "RXDATA2" "BIDIRECTIONAL LED" 392.75,296 r0 top
LED65 "BB_DEBUG_0" "BIDIRECTIONAL LED" 295.5,196.5 r180 top
LED66 "BB_DEBUG_8" "BIDIRECTIONAL LED" 295.5,216.5 r180 top
LED67 "LED_AUX_0" "BIDIRECTIONAL LED" 142.5,339.25 r90 top
LED68 "LED_AUX_8" "BIDIRECTIONAL LED" 162.5,339.25 r90 top
LED69 "AFSK2_DET" "BIDIRECTIONAL LED" 174.25,252.75 r180 top
LED70 "TXEN2" "BIDIRECTIONAL LED" 392.75,293.5 r0 top
LED71 "BB_DEBUG_1" "BIDIRECTIONAL LED" 295.5,199 r180 top
LED72 "BB_DEBUG_9" "BIDIRECTIONAL LED" 295.5,219 r180 top
LED73 "LED_AUX_1" "BIDIRECTIONAL LED" 145,339.25 r90 top
LED74 "LED_AUX_9" "BIDIRECTIONAL LED" 165,339.25 r90 top
LED75 "TXDATA1" "BIDIRECTIONAL LED" 392.75,311 r0 top
LED76 "RX_S/N2" "BIDIRECTIONAL LED" 392.75,291 r0 top
LED77 "BB_DEBUG_2" "BIDIRECTIONAL LED" 295.5,201.5 r180 top
LED78 "BB_DEBUG_10" "BIDIRECTIONAL LED" 295.5,221.5 r180 top
LED79 "LED_AUX_2" "BIDIRECTIONAL LED" 147.5,339.25 r90 top
LED80 "LED_AUX_10" "BIDIRECTIONAL LED" 167.5,339.25 r90 top
LED81 "8V0_RX2" 6-0805_M 367.803,9.165 r0 top
LED82 "RXDATA1" "BIDIRECTIONAL LED" 392.75,308.5 r0 top
LED83 "RXHOLD2" "BIDIRECTIONAL LED" 392.75,288.5 r0 top
LED84 "BB_DEBUG_3" "BIDIRECTIONAL LED" 295.5,204 r180 top
LED85 "BB_DEBUG_11" "BIDIRECTIONAL LED" 295.5,224 r180 top
LED86 "LED_AUX_3" "BIDIRECTIONAL LED" 150,339.25 r90 top
LED87 "LED_AUX_11" "BIDIRECTIONAL LED" 170,339.25 r90 top
LED88 "TXEN1" "BIDIRECTIONAL LED" 392.75,306 r0 top
LED89 "BBONE_I2C2_SDA" "BIDIRECTIONAL LED" 123.25,146.75 r270 top
LED90 "BB_DEBUG_4" "BIDIRECTIONAL LED" 295.5,206.5 r180 top
LED91 "BB_DEBUG_12" "BIDIRECTIONAL LED" 295.5,226.5 r180 top
LED92 "LED_AUX_4" "BIDIRECTIONAL LED" 152.5,339.25 r90 top
LED93 "LED_AUX_12" "BIDIRECTIONAL LED" 172.5,339.25 r90 top
LED94 "RX_S/N1" "BIDIRECTIONAL LED" 392.75,303.5 r0 top
LED95 "BBONE_I2C2_SCL" "BIDIRECTIONAL LED" 120.75,146.75 r270 top
LED96 "BB_DEBUG_5" "BIDIRECTIONAL LED" 295.5,209 r180 top
LED97 "BB_DEBUG_13" "BIDIRECTIONAL LED" 295.5,229 r180 top
LED98 "LED_AUX_5" "BIDIRECTIONAL LED" 155,339.25 r90 top
LED99 "LED_AUX_13" "BIDIRECTIONAL LED" 175,339.25 r90 top
LED100 "VVAR_TX2" 6-0805_M 367.803,14.245 r0 top
LED101 "RXHOLD1" "BIDIRECTIONAL LED" 392.75,301 r0 top
LED102 "3V3_UNREG_PG" "BIDIRECTIONAL LED" 367.808,47.465 r180 top
LED103 "BB_DEBUG_6" "BIDIRECTIONAL LED" 295.5,211.5 r180 top
LED104 "BB_DEBUG_14" "BIDIRECTIONAL LED" 295.5,231.5 r180 top
LED105 "LED_AUX_6" "BIDIRECTIONAL LED" 157.5,339.25 r90 top
LED106 "LED_AUX_14" "BIDIRECTIONAL LED" 177.5,339.25 r90 top
LED107 "TXDATA2" "BIDIRECTIONAL LED" 392.75,298.5 r0 top
LED108 "5V0_UNREG_PG" "BIDIRECTIONAL LED" 367.808,44.865 r180 top
LED109 "BB_DEBUG_7" "BIDIRECTIONAL LED" 295.5,214 r180 top
LED111 "LED_AUX_7" "BIDIRECTIONAL LED" 160,339.25 r90 top
LED112 "LED_AUX_15" "BIDIRECTIONAL LED" 180,339.25 r90 top
LOGO "" LOGO 394.1,69.8 r270 top
P1 "Jumper_Filter" Jumper_filter#1 398.098,267.445 r270 top
P2 "Jumper_Filter" Jumper_filter#1 395.558,267.445 r270 top
P3 "Jumper_Filter" Jumper_filter#1 393.018,267.445 r270 top
P4 "Jumper_Filter" Jumper_filter#1 390.478,267.445 r270 top
P5 "Jumper_Filter" Jumper_filter#1 387.938,267.445 r270 top
P6 "Jumper_Filter" Jumper_filter#1 385.398,267.445 r270 top
P7 "Jumper_Filter" Jumper_filter#1 382.858,267.445 r270 top
P8 "Jumper_Filter" Jumper_filter#1 380.318,267.445 r270 top
P9 "Jumper_Filter" Jumper_filter#2 377.778,267.445 r270 top
P10 "Jumper_Filter" Jumper_filter#1 375.238,267.445 r270 top
P11 "Jumper_Filter" Jumper_filter#1 372.698,267.445 r270 top
P12 "Jumper_Filter" Jumper_filter#1 370.158,267.445 r270 top
P13 "Jumper_Filter" Jumper_filter#1 367.618,267.445 r270 top
P14 "Jumper_Filter" Jumper_filter#1 365.078,267.445 r270 top
P15 "Jumper_Filter" Jumper_filter#3 362.538,267.445 r270 top
P16 "Jumper_Filter" Jumper_filter#1 359.998,267.445 r270 top
P17 "Jumper_Filter" Jumper_filter#1 357.458,267.445 r270 top
P18 "Jumper_Filter" Jumper_filter#1 354.918,267.445 r270 top
P19 "Jumper_Filter" Jumper_filter#3 352.378,267.445 r270 top
P20 "Jumper_Filter" Jumper_filter#1 349.838,267.445 r270 top
P21 "Jumper_Filter" Jumper_filter#1 347.298,267.445 r270 top
P22 "Jumper_Filter" Jumper_filter#1 344.758,267.445 r270 top
P23 "Jumper_Filter" Jumper_filter#1 342.218,267.445 r270 top
P24 "Jumper_Filter" Jumper_filter#1 339.678,267.445 r270 top
P25 "Jumper_Filter" Jumper_filter#1 337.138,267.445 r270 top
P26 "Jumper_Filter" Jumper_filter#1 334.598,267.445 r270 top
P27 "Jumper_Filter" Jumper_filter#1 332.058,267.445 r270 top
P28 "Jumper_Filter" Jumper_filter#1 329.518,267.445 r270 top
P29 "Jumper_Filter" Jumper_filter#1 326.978,267.445 r270 top
P30 "Jumper_Filter" Jumper_filter#1 324.438,267.445 r270 top
P31 "Jumper_Filter" Jumper_filter#1 321.898,267.445 r270 top
P32 "Jumper_Filter" Jumper_filter#1 319.358,267.445 r270 top
P33 "Jumper_Filter" Jumper_filter#1 316.818,267.445 r270 top
P34 "Jumper_Filter" Jumper_filter#1 314.278,267.445 r270 top
P35 "Jumper_Filter" Jumper_filter#1 311.738,267.445 r270 top
P36 "Jumper_Filter" Jumper_filter#1 309.198,267.445 r270 top
P37 "Jumper_Filter" Jumper_filter#1 306.658,267.445 r270 top
P38 "Jumper_Filter" Jumper_filter#1 304.118,267.445 r270 top
P39 "Jumper_Filter" Jumper_filter#1 301.578,267.445 r270 top
P40 "Jumper_Filter" Jumper_filter#1 299.038,267.445 r270 top
P41 "Jumper_Filter" Jumper_filter#1 296.498,267.445 r270 top
P42 "Jumper_Filter" Jumper_filter#1 293.958,267.445 r270 top
P43 "Jumper_Filter" Jumper_filter#1 291.418,267.445 r270 top
P44 "Jumper_Filter" Jumper_filter#1 288.878,267.445 r270 top
P45 "Jumper_Filter" Jumper_filter#1 286.338,267.445 r270 top
P46 "Jumper_Filter" Jumper_filter#1 283.798,267.445 r270 top
P47 "Jumper_Filter" Jumper_filter#4 398.098,160.765 r90 top
P48 "Jumper_Filter" Jumper_filter#4 395.558,160.765 r90 top
P49 "Jumper_Filter" Jumper_filter#4 393.018,160.765 r90 top
P50 "Jumper_Filter" Jumper_filter#4 390.478,160.765 r90 top
P51 "Jumper_Filter" Jumper_filter#4 387.938,160.765 r90 top
P52 "Jumper_Filter" Jumper_filter#4 385.398,160.765 r90 top
P53 "Jumper_Filter" Jumper_filter#4 382.858,160.765 r90 top
P54 "Jumper_Filter" Jumper_filter#4 380.318,160.765 r90 top
P55 "Jumper_Filter" Jumper_filter#4 377.778,160.765 r90 top
P56 "Jumper_Filter" Jumper_filter#4 375.238,160.765 r90 top
P57 "Jumper_Filter" Jumper_filter#4 372.698,160.765 r90 top
P58 "Jumper_Filter" Jumper_filter#4 370.158,160.765 r90 top
P59 "Jumper_Filter" Jumper_filter#4 367.618,160.765 r90 top
P60 "Jumper_Filter" Jumper_filter#4 365.078,160.765 r90 top
P61 "Jumper_Filter" Jumper_filter#4 362.538,160.765 r90 top
P62 "Jumper_Filter" Jumper_filter#4 359.998,160.765 r90 top
P63 "Jumper_Filter" Jumper_filter#4 357.458,160.765 r90 top
P64 "Jumper_Filter" Jumper_filter#4 354.918,160.765 r90 top
P65 "Jumper_Filter" Jumper_filter#4 352.378,160.765 r90 top
P66 "Jumper_Filter" Jumper_filter#4 349.838,160.765 r90 top
P67 "Jumper_Filter" Jumper_filter#4 347.298,160.765 r90 top
P68 "Jumper_Filter" Jumper_filter#4 344.758,160.765 r90 top
P69 "Jumper_Filter" Jumper_filter#4 342.218,160.765 r90 top
P70 "Jumper_Filter" Jumper_filter#4 339.678,160.765 r90 top
P71 "Jumper_Filter" Jumper_filter#4 337.138,160.765 r90 top
P72 "Jumper_Filter" Jumper_filter#4 334.598,160.765 r90 top
P73 "Jumper_Filter" Jumper_filter#4 332.058,160.765 r90 top
P74 "Jumper_Filter" Jumper_filter#4 329.518,160.765 r90 top
P75 "Jumper_Filter" Jumper_filter#4 326.978,160.765 r90 top
P76 "Jumper_Filter" Jumper_filter#4 324.438,160.765 r90 top
P77 "Jumper_Filter" Jumper_filter#4 321.898,160.765 r90 top
P78 "Jumper_Filter" Jumper_filter#4 319.358,160.765 r90 top
P79 "Jumper_Filter" Jumper_filter#4 316.818,160.765 r90 top
P80 "Jumper_Filter" Jumper_filter#4 314.278,160.765 r90 top
P81 "Jumper_Filter" Jumper_filter#4 311.738,160.765 r90 top
P82 "Jumper_Filter" Jumper_filter#4 309.198,160.765 r90 top
P83 "Jumper_Filter" Jumper_filter#4 306.658,160.765 r90 top
P84 "Jumper_Filter" Jumper_filter#4 304.118,160.765 r90 top
P85 "Jumper_Filter" Jumper_filter#4 301.578,160.765 r90 top
P86 "Jumper_Filter" Jumper_filter#4 299.038,160.765 r90 top
P87 "Jumper_Filter" Jumper_filter#4 296.498,160.765 r90 top
P88 "Jumper_Filter" Jumper_filter#4 293.958,160.765 r90 top
P89 "Jumper_Filter" Jumper_filter#4 291.418,160.765 r90 top
P90 "Jumper_Filter" Jumper_filter#4 288.878,160.765 r90 top
P91 "Jumper_Filter" Jumper_filter#4 286.338,160.765 r90 top
P92 "Jumper_Filter" Jumper_filter#4 283.798,160.765 r90 top
P93 "Jumper_Filter" Jumper_filter#1 410.798,224.265 r180 top
P94 "Jumper_Filter" Jumper_filter#1 410.798,221.725 r180 top
P95 "Jumper_Filter" Jumper_filter#1 410.798,226.805 r180 top
P96 "Jumper_Filter" Jumper_filter#1 410.798,219.185 r180 top
P97 "Jumper_Filter" Jumper_filter#1 410.798,229.345 r180 top
P98 "Jumper_Filter" Jumper_filter#1 410.798,216.645 r180 top
P99 "Jumper_Filter" Jumper_filter#1 410.798,231.885 r180 top
P100 "Jumper_Filter" Jumper_filter#1 410.798,214.105 r180 top
P101 "Jumper_Filter" Jumper_filter#1 410.798,234.425 r180 top
P102 "Jumper_Filter" Jumper_filter#5 410.798,211.565 r180 top
P103 "Jumper_Filter" Jumper_filter#1 230.99,206.992 r90 top
P104 "Jumper_Filter" Jumper_filter#6 233.53,206.992 r90 top
P105 "Jumper_Filter" Jumper_filter#6 236.07,206.992 r90 top
P106 "Jumper_Filter" Jumper_filter#6 238.61,206.992 r90 top
P107 "Jumper_Filter" Jumper_filter#6 241.15,206.992 r90 top
P108 "Jumper_Filter" Jumper_filter#6 243.69,206.992 r90 top
P109 "Jumper_Filter" Jumper_filter#7 215.75,206.992 r90 top
P110 "Jumper_Filter" Jumper_filter#7 218.29,206.992 r90 top
P111 "Jumper_Filter" Jumper_filter#7 220.83,206.992 r90 top
P112 "Jumper_Filter" Jumper_filter#7 223.37,206.992 r90 top
P113 "Jumper_Filter" Jumper_filter#7 225.91,206.992 r90 top
P114 "Jumper_Filter" Jumper_filter#1 228.45,206.992 r90 top
P115 "Jumper_Filter" Jumper_filter#1 286.362,306.052 r180 top
P116 "Jumper_Filter" Jumper_filter#1 286.362,295.892 r180 top
P117 "Jumper_Filter" Jumper_filter#1 286.362,300.972 r180 top
P118 "Jumper_Filter" Jumper_filter#1 286.362,290.812 r180 top
P119 "Jumper_Filter" Jumper_filter#1 156.822,303.512 r0 top
P120 "Jumper_Filter" Jumper_filter#1 156.822,298.432 r0 top
P121 "Jumper_Filter" Jumper_filter#1 156.822,293.352 r0 top
P122 "Jumper_Filter" Jumper_filter#1 156.822,288.272 r0 top
P123 "Jumper_Filter" Jumper_filter#1 286.362,303.512 r180 top
P124 "Jumper_Filter" Jumper_filter#1 286.362,298.432 r180 top
P125 "Jumper_Filter" Jumper_filter#1 286.362,293.352 r180 top
P126 "Jumper_Filter" Jumper_filter#1 286.362,288.272 r180 top
P127 "Jumper_Filter" Jumper_filter#7 213.21,206.992 r90 top
P128 "Jumper_Filter" Jumper_filter#8 205.59,206.992 r90 top
P129 "Jumper_Filter" Jumper_filter#9 210.67,206.992 r90 top
P130 "Jumper_Filter" Jumper_filter#1 156.822,300.972 r0 top
P131 "Jumper_Filter" Jumper_filter#1 156.822,285.732 r0 top
P132 "Jumper_Filter" Jumper_filter#1 156.822,290.812 r0 top
P133 "Jumper_Filter" Jumper_filter#1 156.822,295.892 r0 top
P134 "Jumper_Filter" Jumper_filter#1 208.13,206.992 r90 top
P135 "Jumper_Filter" Jumper_filter#1 231.482,332.468 r270 top
P136 "Jumper_Filter" Jumper_filter#1 228.942,332.468 r270 top
P137 "Jumper_Filter" Jumper_filter#1 226.402,332.468 r270 top
P138 "Jumper_Filter" Jumper_filter#1 223.862,332.468 r270 top
P139 "Jumper_Filter" Jumper_filter#1 221.322,332.468 r270 top
P140 "Jumper_Filter" Jumper_filter#1 218.782,332.468 r270 top
P141 "Jumper_Filter" Jumper_filter#1 216.242,332.468 r270 top
P142 "Jumper_Filter" Jumper_filter#1 213.702,332.468 r270 top
P143 "Jumper_Filter" Jumper_filter#1 211.162,332.468 r270 top
P144 "Jumper_Filter" Jumper_filter#1 208.622,332.468 r270 top
P145 "Jumper_Filter" Jumper_filter#1 206.082,332.468 r270 top
P146 "Jumper_Filter" Jumper_filter#1 203.542,332.468 r270 top
P147 "Jumper_Filter" Jumper_filter#1 241.642,332.468 r270 top
P148 "Jumper_Filter" Jumper_filter#1 239.102,332.468 r270 top
P149 "Jumper_Filter" Jumper_filter#1 236.562,332.468 r270 top
P150 "Jumper_Filter" Jumper_filter#1 234.022,332.468 r270 top
P151 "Jumper_Filter" Jumper_filter#1 320.908,343.53 r270 top
P152 "Jumper_Filter" Jumper_filter#1 315.828,343.53 r270 top
P153 "Jumper_Filter" Jumper_filter#1 310.748,343.53 r270 top
P154 "Jumper_Filter" Jumper_filter#1 305.668,343.53 r270 top
P155 "Jumper_Filter" Jumper_filter#1 300.588,343.53 r270 top
P156 "Jumper_Filter" Jumper_filter#1 371.708,343.53 r270 top
P157 "Jumper_Filter" Jumper_filter#1 366.628,343.53 r270 top
P158 "Jumper_Filter" Jumper_filter#1 361.548,343.53 r270 top
P159 "Jumper_Filter" Jumper_filter#1 356.468,343.53 r270 top
P160 "Jumper_Filter" Jumper_filter#1 351.388,343.53 r270 top
P161 "Jumper_Filter" Jumper_filter#1 325.988,343.53 r270 top
P162 "Jumper_Filter" Jumper_filter#1 331.068,343.53 r270 top
P163 "Jumper_Filter" Jumper_filter#1 336.148,343.53 r270 top
P164 "Jumper_Filter" Jumper_filter#1 341.228,343.53 r270 top
P165 "Jumper_Filter" Jumper_filter#1 323.448,343.53 r270 top
P166 "Jumper_Filter" Jumper_filter#1 318.368,343.53 r270 top
P167 "Jumper_Filter" Jumper_filter#1 313.288,343.53 r270 top
P168 "Jumper_Filter" Jumper_filter#1 308.208,343.53 r270 top
P169 "Jumper_Filter" Jumper_filter#1 303.128,343.53 r270 top
P170 "Jumper_Filter" Jumper_filter#1 298.048,343.53 r270 top
P171 "Jumper_Filter" Jumper_filter#1 374.248,343.53 r270 top
P172 "Jumper_Filter" Jumper_filter#1 369.168,343.53 r270 top
P173 "Jumper_Filter" Jumper_filter#1 364.088,343.53 r270 top
P174 "Jumper_Filter" Jumper_filter#1 359.008,343.53 r270 top
P175 "Jumper_Filter" Jumper_filter#1 353.928,343.53 r270 top
P176 "Jumper_Filter" Jumper_filter#1 348.848,343.53 r270 top
P177 "Jumper_Filter" Jumper_filter#1 290.428,343.53 r270 top
P178 "Jumper_Filter" Jumper_filter#1 292.968,343.53 r270 top
P179 "Jumper_Filter" Jumper_filter#1 346.308,343.53 r270 top
P180 "Jumper_Filter" Jumper_filter#1 295.508,343.53 r270 top
P181 "Jumper_Filter" Jumper_filter#1 328.528,343.53 r270 top
P182 "Jumper_Filter" Jumper_filter#1 333.608,343.53 r270 top
P183 "Jumper_Filter" Jumper_filter#1 338.688,343.53 r270 top
P184 "Jumper_Filter" Jumper_filter#1 343.768,343.53 r270 top
P185 "Jumper" Jumper 15.443,287.336 r180 top
P186 "Jumper" Jumper 15.443,284.796 r180 top
P187 "Jumper" Jumper 15.443,292.416 r180 top
P188 "Jumper" Jumper 15.443,289.876 r180 top
P189 "Jumper" Jumper 15.443,294.956 r180 top
P190 "Jumper" Jumper 15.443,300.036 r180 top
P191 "Jumper" Jumper 15.443,297.496 r180 top
P192 "Jumper" Jumper 15.443,305.116 r180 top
P193 "Jumper" Jumper 15.443,302.576 r180 top
P194 "Jumper" Jumper 15.443,259.396 r180 top
P195 "Jumper" Jumper 15.443,256.856 r180 top
P196 "Jumper" Jumper 15.443,264.476 r180 top
P197 "Jumper" Jumper 15.443,261.936 r180 top
P198 "Jumper" Jumper 15.443,267.016 r180 top
P199 "Jumper" Jumper 15.443,272.096 r180 top
P200 "Jumper" Jumper 15.443,269.556 r180 top
P201 "Jumper" Jumper 15.443,277.176 r180 top
P202 "Jumper" Jumper 15.443,274.636 r180 top
P203 "Jumper_Filter" Jumper_filter#1 152.734,207.374 r180 top
P204 "Jumper_Filter" Jumper_filter#1 152.734,212.454 r180 top
P205 "Jumper_Filter" Jumper_filter#1 152.734,217.534 r180 top
P206 "Jumper_Filter" Jumper_filter#1 152.734,222.614 r180 top
P207 "Jumper_Filter" Jumper_filter#1 152.734,227.694 r180 top
P208 "Jumper_Filter" Jumper_filter#1 152.734,232.774 r180 top
P209 "Jumper_Filter" Jumper_filter#1 152.734,237.854 r180 top
P210 "Jumper_Filter" Jumper_filter#1 152.734,242.934 r180 top
P211 "Jumper_Filter" Jumper_filter#1 152.734,248.014 r180 top
P212 "Jumper_Filter" Jumper_filter#1 152.734,253.094 r180 top
P213 "Jumper_Filter" Jumper_filter#1 152.734,258.174 r180 top
P214 "Jumper_Filter" Jumper_filter#1 152.734,263.254 r180 top
P215 "Jumper_Filter" Jumper_filter#1 152.734,268.334 r180 top
P216 "Jumper_Filter" Jumper_filter#1 152.734,273.414 r180 top
P217 "Jumper_Filter" Jumper_filter#1 152.734,278.494 r180 top
P218 "Jumper_Filter" Jumper_filter#1 152.734,283.574 r180 top
P219 "Jumper_Filter" Jumper_filter#1 152.734,288.654 r180 top
P220 "Jumper_Filter" Jumper_filter#1 152.734,293.734 r180 top
P221 "Jumper_Filter" Jumper_filter#1 152.734,298.814 r180 top
P222 "Jumper_Filter" Jumper_filter#1 152.734,303.894 r180 top
P223 "Jumper_Filter" Jumper_filter#1 152.734,181.974 r180 top
P224 "Jumper_Filter" Jumper_filter#1 152.734,187.054 r180 top
P225 "Jumper_Filter" Jumper_filter#1 152.734,192.134 r180 top
P226 "Jumper_Filter" Jumper_filter#1 152.734,209.914 r180 top
P227 "Jumper_Filter" Jumper_filter#1 152.734,214.994 r180 top
P228 "Jumper_Filter" Jumper_filter#1 152.734,220.074 r180 top
P229 "Jumper_Filter" Jumper_filter#1 152.734,225.154 r180 top
P230 "Jumper_Filter" Jumper_filter#1 152.734,230.234 r180 top
P231 "Jumper_Filter" Jumper_filter#1 152.734,235.314 r180 top
P232 "Jumper_Filter" Jumper_filter#1 152.734,240.394 r180 top
P233 "Jumper_Filter" Jumper_filter#1 152.734,245.474 r180 top
P234 "Jumper_Filter" Jumper_filter#10 152.734,250.554 r180 top
P235 "Jumper_Filter" Jumper_filter#11 152.734,255.634 r180 top
P236 "Jumper_Filter" Jumper_filter#1 152.734,260.714 r180 top
P237 "Jumper_Filter" Jumper_filter#12 152.734,265.794 r180 top
P238 "Jumper_Filter" Jumper_filter#12 152.734,270.874 r180 top
P239 "Jumper_Filter" Jumper_filter#12 152.734,275.954 r180 top
P240 "Jumper_Filter" Jumper_filter#12 152.734,281.034 r180 top
P241 "Jumper_Filter" Jumper_filter#12 152.734,286.114 r180 top
P242 "Jumper_Filter" Jumper_filter#12 152.734,291.194 r180 top
P243 "Jumper_Filter" Jumper_filter#12 152.734,296.274 r180 top
P244 "Jumper_Filter" Jumper_filter#12 152.734,301.354 r180 top
P245 "Jumper_Filter" Jumper_filter#1 152.734,306.434 r180 top
P246 "Jumper_Filter" Jumper_filter#12 152.734,184.514 r180 top
P247 "Jumper_Filter" Jumper_filter#12 152.734,189.594 r180 top
P248 "Jumper_Filter" Jumper_filter#12 152.734,194.674 r180 top
P249 "Jumper_Filter" Jumper_filter#12 40.974,334.374 r270 top
P250 "Jumper_Filter" Jumper_filter#12 46.054,334.374 r270 top
P251 "Jumper_Filter" Jumper_filter#12 51.134,334.374 r270 top
P252 "Jumper_Filter" Jumper_filter#12 56.214,334.374 r270 top
P253 "Jumper_Filter" Jumper_filter#12 61.294,334.374 r270 top
P254 "Jumper_Filter" Jumper_filter#12 66.374,334.374 r270 top
P255 "Jumper_Filter" Jumper_filter#12 71.454,334.374 r270 top
P256 "Jumper_Filter" Jumper_filter#12 76.534,334.374 r270 top
P257 "Jumper_Filter" Jumper_filter#12 81.614,334.374 r270 top
P258 "Jumper_Filter" Jumper_filter#12 86.694,334.374 r270 top
P259 "Jumper_Filter" Jumper_filter#12 91.774,334.374 r270 top
P260 "Jumper_Filter" Jumper_filter#12 96.854,334.374 r270 top
P261 "Jumper_Filter" Jumper_filter#12 101.934,334.374 r270 top
P262 "Jumper_Filter" Jumper_filter#12 107.014,334.374 r270 top
P263 "Jumper_Filter" Jumper_filter#12 112.094,334.374 r270 top
P264 "Jumper_Filter" Jumper_filter#12 117.174,334.374 r270 top
P265 "Jumper_Filter" Jumper_filter#12 122.254,334.374 r270 top
P266 "Jumper_Filter" Jumper_filter#12 127.334,334.374 r270 top
P267 "Jumper_Filter" Jumper_filter#12 132.414,334.374 r270 top
P268 "Jumper_Filter" Jumper_filter#12 137.494,334.374 r270 top
P269 "Jumper_Filter" Jumper_filter#12 38.434,334.374 r270 top
P270 "Jumper_Filter" Jumper_filter#12 43.514,334.374 r270 top
P271 "Jumper_Filter" Jumper_filter#12 48.594,334.374 r270 top
P272 "Jumper_Filter" Jumper_filter#12 53.674,334.374 r270 top
P273 "Jumper_Filter" Jumper_filter#12 58.754,334.374 r270 top
P274 "Jumper_Filter" Jumper_filter#12 63.834,334.374 r270 top
P275 "Jumper_Filter" Jumper_filter#12 68.914,334.374 r270 top
P276 "Jumper_Filter" Jumper_filter#12 73.994,334.374 r270 top
P277 "Jumper_Filter" Jumper_filter#12 79.074,334.374 r270 top
P278 "Jumper_Filter" Jumper_filter#12 84.154,334.374 r270 top
P279 "Jumper_Filter" Jumper_filter#12 89.234,334.374 r270 top
P280 "Jumper_Filter" Jumper_filter#12 94.314,334.374 r270 top
P281 "Jumper_Filter" Jumper_filter#12 99.394,334.374 r270 top
P282 "Jumper_Filter" Jumper_filter#13 104.474,334.374 r270 top
P283 "Jumper_Filter" Jumper_filter#12 109.554,334.374 r270 top
P284 "Jumper_Filter" Jumper_filter#12 114.634,334.374 r270 top
P285 "Jumper_Filter" Jumper_filter#12 119.714,334.374 r270 top
P286 "Jumper_Filter" Jumper_filter#12 124.794,334.374 r270 top
P287 "Jumper_Filter" Jumper_filter#12 129.874,334.374 r270 top
P288 "Jumper_Filter" Jumper_filter#12 134.954,334.374 r270 top
P289 "Jumper_Filter" Jumper_filter#1 31.439,161.92 r90 top
P290 "Jumper_Filter" Jumper_filter#1 33.979,161.92 r90 top
P291 "Jumper_Filter" Jumper_filter#1 36.519,161.92 r90 top
P292 "Jumper_Filter" Jumper_filter#1 39.059,161.92 r90 top
P293 "Jumper_Filter" Jumper_filter#12 20.654,306.434 r0 top
P294 "Jumper_Filter" Jumper_filter#12 20.654,301.354 r0 top
P295 "Jumper_Filter" Jumper_filter#12 20.654,296.274 r0 top
P296 "Jumper_Filter" Jumper_filter#12 20.654,291.194 r0 top
P297 "Jumper_Filter" Jumper_filter#12 20.654,286.114 r0 top
P298 "Jumper_Filter" Jumper_filter#12 20.654,281.034 r0 top
P299 "Jumper_Filter" Jumper_filter#12 20.654,275.954 r0 top
P300 "Jumper_Filter" Jumper_filter#12 20.654,270.874 r0 top
P301 "Jumper_Filter" Jumper_filter#12 20.654,265.794 r0 top
P302 "Jumper_Filter" Jumper_filter#12 20.654,260.714 r0 top
P303 "Jumper_Filter" Jumper_filter#12 20.654,255.634 r0 top
P304 "Jumper_Filter" Jumper_filter#12 20.654,250.554 r0 top
P305 "Jumper_Filter" Jumper_filter#12 20.654,245.474 r0 top
P306 "Jumper_Filter" Jumper_filter#12 20.654,240.394 r0 top
P307 "Jumper_Filter" Jumper_filter#12 20.654,235.314 r0 top
P308 "Jumper_Filter" Jumper_filter#12 20.654,230.234 r0 top
P309 "Jumper_Filter" Jumper_filter#12 20.654,225.154 r0 top
P310 "Jumper_Filter" Jumper_filter#12 20.654,220.074 r0 top
P311 "Jumper_Filter" Jumper_filter#12 20.654,214.994 r0 top
P312 "Jumper_Filter" Jumper_filter#12 20.654,209.914 r0 top
P313 "Jumper_Filter" Jumper_filter#4 31.439,202.56 r270 top
P314 "Jumper_Filter" Jumper_filter#4 33.979,202.56 r270 top
P315 "Jumper_Filter" Jumper_filter#4 36.519,202.56 r270 top
P316 "Jumper_Filter" Jumper_filter#4 39.059,202.56 r270 top
P317 "Jumper_Filter" Jumper_filter#12 20.654,303.894 r0 top
P318 "Jumper_Filter" Jumper_filter#12 20.654,298.814 r0 top
P319 "Jumper_Filter" Jumper_filter#12 20.654,293.734 r0 top
P320 "Jumper_Filter" Jumper_filter#12 20.654,288.654 r0 top
P321 "Jumper_Filter" Jumper_filter#12 20.654,283.574 r0 top
P322 "Jumper_Filter" Jumper_filter#12 20.654,278.494 r0 top
P323 "Jumper_Filter" Jumper_filter#12 20.654,273.414 r0 top
P324 "Jumper_Filter" Jumper_filter#12 20.654,268.334 r0 top
P325 "Jumper_Filter" Jumper_filter#12 20.654,263.254 r0 top
P326 "Jumper_Filter" Jumper_filter#12 20.654,258.174 r0 top
P327 "Jumper_Filter" Jumper_filter#12 20.654,253.094 r0 top
P328 "Jumper_Filter" Jumper_filter#12 20.654,248.014 r0 top
P329 "Jumper_Filter" Jumper_filter#12 20.654,242.934 r0 top
P330 "Jumper_Filter" Jumper_filter#12 20.654,237.854 r0 top
P331 "Jumper_Filter" Jumper_filter#12 20.654,232.774 r0 top
P332 "Jumper_Filter" Jumper_filter#12 20.654,227.694 r0 top
P333 "Jumper_Filter" Jumper_filter#12 20.654,222.614 r0 top
P334 "Jumper_Filter" Jumper_filter#12 20.654,217.534 r0 top
P335 "Jumper_Filter" Jumper_filter#12 20.654,212.454 r0 top
P336 "Jumper_Filter" Jumper_filter#12 20.654,207.374 r0 top
P337 "Jumper_Filter" Jumper_filter#1 140.339,20.836 r90 top
P338 "Jumper_Filter" Jumper_filter#1 137.799,20.836 r90 top
P339 "Jumper_Filter" Jumper_filter#1 145.419,20.836 r90 top
P340 "Jumper_Filter" Jumper_filter#1 142.879,20.836 r90 top
P341 "Jumper_Filter" Jumper_filter#1 153.039,20.836 r90 top
P342 "Jumper_Filter" Jumper_filter#1 150.499,20.836 r90 top
P343 "Jumper_Filter" Jumper_filter#1 147.959,20.836 r90 top
P344 "Jumper_Filter" Jumper_filter#1 155.579,20.836 r90 top
P345 "Jumper_Filter" Jumper_filter#8 99.699,20.836 r90 top
P346 "Jumper_Filter" Jumper_filter#1 97.159,20.836 r90 top
P347 "Jumper_Filter" Jumper_filter#1 94.619,20.836 r90 top
P348 "Jumper_Filter" Jumper_filter#1 92.079,20.836 r90 top
P349 "Jumper_Filter" Jumper_filter#1 107.319,20.836 r90 top
P350 "Jumper_Filter" Jumper_filter#8 104.779,20.836 r90 top
P351 "Jumper_Filter" Jumper_filter#1 102.239,20.836 r90 top
P352 "Jumper_Filter" Jumper_filter#1 109.859,20.836 r90 top
P353 "Jumper_Filter" Jumper_filter#1 191.139,20.836 r90 top
P354 "Jumper_Filter" Jumper_filter#1 188.599,20.836 r90 top
P355 "Jumper_Filter" Jumper_filter#1 186.059,20.836 r90 top
P356 "Jumper_Filter" Jumper_filter#1 183.519,20.836 r90 top
P357 "Jumper_Filter" Jumper_filter#1 196.219,20.836 r90 top
P358 "Jumper_Filter" Jumper_filter#1 198.759,20.836 r90 top
P359 "Jumper_Filter" Jumper_filter#1 193.679,20.836 r90 top
P360 "Jumper_Filter" Jumper_filter#1 201.299,20.836 r90 top
P361 "Jumper_Filter" Jumper_filter#1 20.451,126.5 r0 top
P362 "Jumper_Filter" Jumper_filter#1 20.451,70.112 r0 top
P363 "Jumper_Filter" Jumper_filter#1 20.451,116.34 r0 top
P364 "Jumper_Filter" Jumper_filter#1 20.451,121.42 r0 top
P365 "Jumper_Filter" Jumper_filter#1 20.451,106.18 r0 top
P366 "Jumper_Filter" Jumper_filter#1 20.451,96.02 r0 top
P367 "Jumper_Filter" Jumper_filter#1 20.451,111.26 r0 top
P368 "Jumper_Filter" Jumper_filter#1 20.451,101.1 r0 top
P369 "Jumper_Filter" Jumper_filter#1 130.179,20.836 r90 top
P370 "Jumper_Filter" Jumper_filter#1 127.639,20.836 r90 top
P371 "Jumper_Filter" Jumper_filter#1 125.099,20.836 r90 top
P372 "Jumper_Filter" Jumper_filter#1 132.719,20.836 r90 top
P373 "Jumper_Filter" Jumper_filter#1 120.019,20.836 r90 top
P374 "Jumper_Filter" Jumper_filter#1 117.479,20.836 r90 top
P375 "Jumper_Filter" Jumper_filter#1 114.939,20.836 r90 top
P376 "Jumper_Filter" Jumper_filter#1 122.559,20.836 r90 top
P377 "Jumper_Filter" Jumper_filter#8 178.439,20.836 r90 top
P378 "Jumper_Filter" Jumper_filter#1 175.899,20.836 r90 top
P379 "Jumper_Filter" Jumper_filter#1 173.359,20.836 r90 top
P380 "Jumper_Filter" Jumper_filter#1 170.819,20.836 r90 top
P381 "Jumper_Filter" Jumper_filter#1 165.739,20.836 r90 top
P382 "Jumper_Filter" Jumper_filter#1 163.199,20.836 r90 top
P383 "Jumper_Filter" Jumper_filter#1 160.659,20.836 r90 top
P384 "Jumper_Filter" Jumper_filter#1 168.279,20.836 r90 top
P385 "Jumper_Filter" Jumper_filter#1 86.999,20.836 r90 top
P386 "Jumper_Filter" Jumper_filter#1 84.459,20.836 r90 top
P387 "Jumper_Filter" Jumper_filter#1 81.919,20.836 r90 top
P388 "Jumper_Filter" Jumper_filter#1 79.379,20.836 r90 top
P389 "Jumper_Filter" Jumper_filter#1 74.299,20.836 r90 top
P390 "Jumper_Filter" Jumper_filter#1 71.759,20.836 r90 top
P391 "Jumper_Filter" Jumper_filter#8 69.219,20.836 r90 top
P392 "Jumper_Filter" Jumper_filter#1 76.839,20.836 r90 top
P393 "Jumper_Filter" Jumper_filter#1 20.451,134.12 r0 top
P394 "Jumper_Filter" Jumper_filter#1 20.451,80.272 r0 top
P395 "Jumper_Filter" Jumper_filter#1 20.451,131.58 r0 top
P396 "Jumper_Filter" Jumper_filter#1 20.451,98.56 r0 top
P397 "Jumper_Filter" Jumper_filter#1 20.451,72.652 r0 top
P398 "Jumper_Filter" Jumper_filter#1 20.451,82.812 r0 top
P399 "Jumper_Filter" Jumper_filter#1 20.451,77.732 r0 top
P400 "Jumper_Filter" Jumper_filter#1 20.451,75.192 r0 top
P401 "Jumper_Filter" Jumper_filter#1 239.399,74.176 r180 top
P402 "Jumper_Filter" Jumper_filter#1 239.399,69.096 r180 top
P403 "Jumper_Filter" Jumper_filter#1 239.399,97.036 r180 top
P404 "Jumper_Filter" Jumper_filter#1 239.399,89.416 r180 top
P405 "Jumper_Filter" Jumper_filter#1 239.399,84.336 r180 top
P406 "Jumper_Filter" Jumper_filter#1 239.399,79.256 r180 top
P407 "Jumper_Filter" Jumper_filter#1 239.399,64.016 r180 top
P408 "Jumper_Filter" Jumper_filter#1 239.399,61.476 r180 top
P409 "Jumper_Filter" Jumper_filter#1 20.451,113.8 r0 top
P410 "Jumper_Filter" Jumper_filter#1 20.451,118.88 r0 top
P411 "Jumper_Filter" Jumper_filter#1 20.451,123.96 r0 top
P412 "Jumper_Filter" Jumper_filter#1 20.451,129.04 r0 top
P413 "Jumper_Filter" Jumper_filter#1 20.451,108.72 r0 top
P414 "Jumper_Filter" Jumper_filter#1 20.451,103.64 r0 top
P415 "Jumper_Filter" Jumper_filter#1 239.399,66.556 r180 top
P416 "Jumper_Filter" Jumper_filter#1 239.399,76.716 r180 top
P417 "Jumper_Filter" Jumper_filter#1 239.399,81.796 r180 top
P418 "Jumper_Filter" Jumper_filter#1 239.399,86.876 r180 top
P419 "Jumper_Filter" Jumper_filter#1 239.399,94.496 r180 top
P420 "Jumper_Filter" Jumper_filter#1 239.399,109.736 r180 top
P421 "Jumper_Filter" Jumper_filter#1 239.399,114.816 r180 top
P422 "Jumper_Filter" Jumper_filter#1 239.399,119.896 r180 top
P423 "Jumper_Filter" Jumper_filter#1 239.399,71.636 r180 top
P424 "Jumper_Filter" Jumper_filter#1 239.399,91.956 r180 top
P425 "Jumper_Filter" Jumper_filter#1 239.399,99.576 r180 top
P426 "Jumper_Filter" Jumper_filter#1 239.399,104.656 r180 top
P427 "Jumper_Filter" Jumper_filter#1 239.399,58.936 r180 top
P428 "Jumper_Filter" Jumper_filter#1 239.399,122.436 r180 top
P429 "Jumper_Filter" Jumper_filter#1 239.399,117.356 r180 top
P430 "Jumper_Filter" Jumper_filter#1 239.399,112.276 r180 top
P431 "Jumper_Filter" Jumper_filter#1 239.399,107.196 r180 top
P432 "Jumper_Filter" Jumper_filter#1 239.399,102.116 r180 top
P433 "Jumper_Filter" Jumper_filter#1 308.69,103.98 r270 top
P434 "Jumper_Filter" Jumper_filter#1 313.77,103.98 r270 top
P435 "Jumper_Filter" Jumper_filter#1 311.23,103.98 r270 top
P436 "Jumper_Filter" Jumper_filter#1 322.287,17.64 r90 top
P437 "Jumper_Filter" Jumper_filter#1 317.207,17.64 r90 top
P438 "Jumper_Filter" Jumper_filter#1 319.747,17.64 r90 top
P439 "Jumper_Filter" Jumper_filter#1 282.034,92.503 r180 top
P440 "Jumper_Filter" Jumper_filter#1 282.034,89.963 r180 top
P441 "Jumper_Filter" Jumper_filter#1 282.034,87.423 r180 top
P442 "Jumper_Filter" Jumper_filter#1 270.971,17.874 r90 top
P443 "Jumper_Filter" Jumper_filter#1 265.891,17.874 r90 top
P444 "Jumper_Filter" Jumper_filter#1 268.431,17.874 r90 top
P445 "Jumper_Filter" Jumper_filter#1 262.462,105.758 r90 top
P446 "Jumper_Filter" Jumper_filter#1 259.922,105.758 r90 top
P447 "Jumper_Filter" Jumper_filter#1 257.382,105.758 r90 top
P448 "Jumper_Filter" Jumper_filter#1 254.842,105.758 r90 top
P449 "Jumper_Filter" Jumper_filter#1 257.128,194.42 r270 top
P450 "Jumper_Filter" Jumper_filter#1 259.668,194.42 r270 top
P451 "Jumper_Filter" Jumper_filter#1 384.184,59.736 r90 top
P452 "Jumper_Filter" Jumper_filter#1 379.104,59.736 r90 top
P453 "Jumper_Filter" Jumper_filter#1 381.644,59.736 r90 top
P454 "Jumper_Filter" Jumper_filter#1 376.564,59.736 r90 top
P455 "Jumper_Filter" Jumper_filter#1 379.104,147.652 r270 top
P456 "Jumper_Filter" Jumper_filter#1 381.644,147.652 r270 top
P457 "Jumper_Filter" Jumper_filter#1 312.127,17.64 r90 top
P458 "Jumper_Filter" Jumper_filter#1 309.587,17.64 r90 top
P459 "Jumper_Filter" Jumper_filter#1 327.367,17.64 r90 top
P460 "Jumper_Filter" Jumper_filter#1 324.827,17.64 r90 top
P461 "Jumper_Filter" Jumper_filter#1 303.61,103.98 r270 top
P462 "Jumper_Filter" Jumper_filter#1 314.667,17.64 r90 top
P463 "Jumper_Filter" Jumper_filter#1 329.907,17.64 r90 top
P464 "Jumper_Filter" Jumper_filter#1 332.447,17.64 r90 top
P465 "Jumper_Filter" Jumper_filter#1 307.047,17.64 r90 top
P466 "Jumper_Filter" Jumper_filter#1 304.507,17.64 r90 top
P467 "Jumper_Filter" Jumper_filter#1 301.07,103.98 r270 top
P468 "Jumper_Filter" Jumper_filter#1 306.15,103.98 r270 top
P469 "Jumper_Filter" Jumper_filter#1 258.271,17.874 r90 top
P470 "Jumper_Filter" Jumper_filter#14 260.811,17.874 r90 top
P471 "Jumper_Filter" Jumper_filter#1 273.511,17.874 r90 top
P472 "Jumper_Filter" Jumper_filter#1 276.051,17.874 r90 top
P473 "Jumper_Filter" Jumper_filter#1 278.591,17.874 r90 top
P474 "Jumper_Filter" Jumper_filter#1 281.131,17.874 r90 top
P475 "Jumper_Filter" Jumper_filter#1 263.351,17.874 r90 top
P476 "Jumper_Filter" Jumper_filter#1 253.191,17.874 r90 top
P477 "Jumper_Filter" Jumper_filter#1 255.731,17.874 r90 top
P478 "Jumper_Filter" Jumper_filter#1 282.034,97.583 r180 top
P479 "Jumper_Filter" Jumper_filter#1 282.034,100.123 r180 top
P480 "Jumper_Filter" Jumper_filter#1 282.034,95.043 r180 top
P481 "Jumper_Filter" Jumper_filter#1 249.508,194.42 r270 top
P482 "Jumper_Filter" Jumper_filter#1 252.048,194.42 r270 top
P483 "Jumper_Filter" Jumper_filter#1 254.588,194.42 r270 top
P484 "Jumper_Filter" Jumper_filter#1 246.968,194.42 r270 top
P485 "Jumper_Filter" Jumper_filter#1 262.208,194.42 r270 top
P486 "Jumper_Filter" Jumper_filter#1 244.428,194.42 r270 top
P487 "Jumper_Filter" Jumper_filter#1 241.888,194.42 r270 top
P488 "Jumper_Filter" Jumper_filter#1 239.348,194.42 r270 top
P489 "Jumper_Filter" Jumper_filter#1 252.302,105.758 r90 top
P490 "Jumper_Filter" Jumper_filter#1 249.762,105.758 r90 top
P491 "Jumper_Filter" Jumper_filter#1 247.222,105.758 r90 top
P492 "Jumper_Filter" Jumper_filter#1 244.682,105.758 r90 top
P493 "Jumper_Filter" Jumper_filter#1 376.564,147.652 r270 top
P494 "Jumper_Filter" Jumper_filter#1 374.024,147.652 r270 top
P495 "Jumper_Filter" Jumper_filter#1 371.484,147.652 r270 top
P496 "Jumper_Filter" Jumper_filter#1 368.944,147.652 r270 top
P497 "Jumper_Filter" Jumper_filter#1 384.184,147.652 r270 top
P498 "Jumper_Filter" Jumper_filter#1 374.024,59.736 r90 top
P499 "Jumper_Filter" Jumper_filter#1 371.484,59.736 r90 top
P500 "Jumper_Filter" Jumper_filter#1 368.944,59.736 r90 top
P501 "Jumper_Filter" Jumper_filter#1 366.404,59.736 r90 top
P502 "Jumper_Filter" Jumper_filter#1 366.404,147.652 r270 top
P503 "Jumper_Filter" Jumper_filter#1 363.864,147.652 r270 top
P504 "Jumper_Filter" Jumper_filter#1 361.324,147.652 r270 top
P505 "Jumper_Filter" Jumper_filter#8 224.759,183.736 r270 top
P506 "Jumper_Filter" Jumper_filter#1 165.688,190.61 r0 top
P507 "Jumper_Filter" Jumper_filter#1 165.688,180.45 r0 top
P508 "Jumper_Filter" Jumper_filter#1 165.688,170.29 r0 top
P509 "Jumper_Filter" Jumper_filter#1 165.688,160.13 r0 top
P510 "Jumper_Filter" Jumper_filter#1 222.219,183.736 r270 top
P511 "Jumper_Filter" Jumper_filter#1 349.46,150.293 r270 top
P512 "Jumper_Filter" Jumper_filter#1 291.418,145.64 r0 top
P513 "Jumper_Filter" Jumper_filter#1 291.418,135.64 r0 top
P514 "Jumper_Filter" Jumper_filter#1 291.418,125.64 r0 top
P515 "Jumper_Filter" Jumper_filter#1 291.418,115.64 r0 top
P516 "Jumper_Filter" Jumper_filter#1 346.92,150.293 r270 top
P517 "Jumper_Filter" Jumper_filter#1 165.688,157.59 r0 top
P518 "Jumper_Filter" Jumper_filter#1 165.688,162.67 r0 top
P519 "Jumper_Filter" Jumper_filter#1 165.688,165.21 r0 top
P520 "Jumper_Filter" Jumper_filter#1 165.688,167.75 r0 top
P521 "Jumper_Filter" Jumper_filter#1 165.688,172.83 r0 top
P522 "Jumper_Filter" Jumper_filter#1 165.688,175.37 r0 top
P523 "Jumper_Filter" Jumper_filter#1 165.688,177.91 r0 top
P524 "Jumper_Filter" Jumper_filter#1 165.688,182.99 r0 top
P525 "Jumper_Filter" Jumper_filter#1 165.688,185.53 r0 top
P526 "Jumper_Filter" Jumper_filter#1 165.688,188.07 r0 top
P527 "Jumper_Filter" Jumper_filter#1 165.688,193.15 r0 top
P528 "Jumper_Filter" Jumper_filter#1 165.688,195.69 r0 top
P529 "Jumper_Filter" Jumper_filter#1 291.418,113.14 r0 top
P530 "Jumper_Filter" Jumper_filter#1 291.418,118.14 r0 top
P531 "Jumper_Filter" Jumper_filter#1 291.418,120.64 r0 top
